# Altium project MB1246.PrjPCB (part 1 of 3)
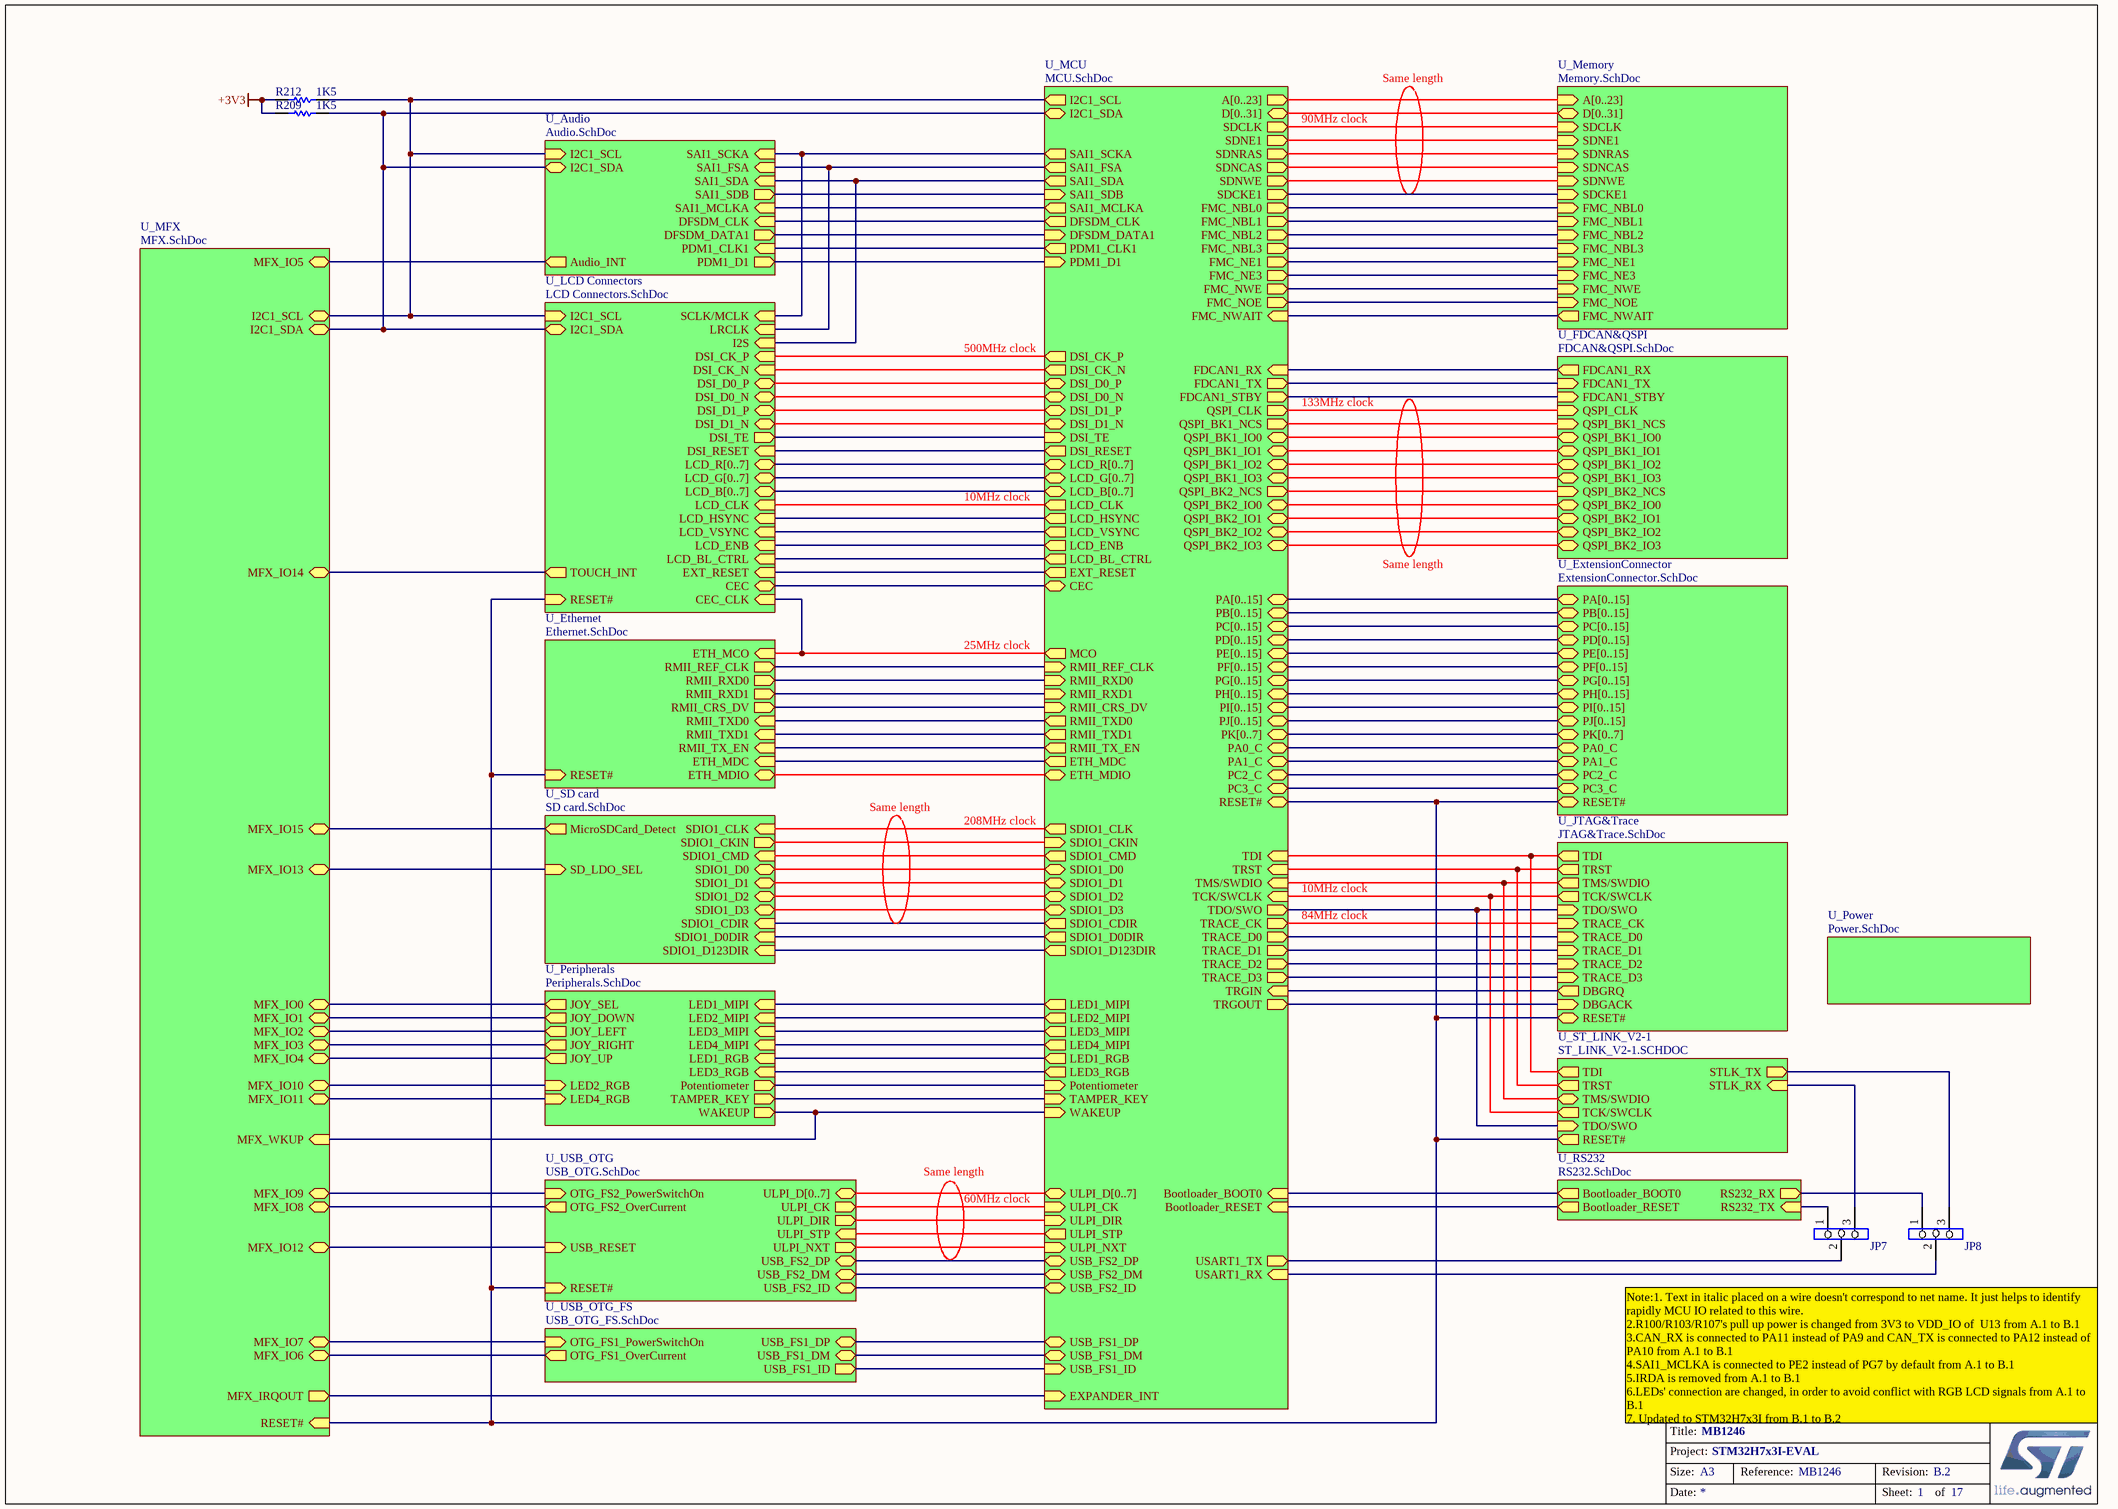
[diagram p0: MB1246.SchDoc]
17 sheets, 671 parts. Net scope: hierarchical (ports join the sheet entries above them; power ports are global).
Sheets:
  MB1246.SchDoc
    U_Audio = Audio.SchDoc
    U_ExtensionConnector = ExtensionConnector.SchDoc
    U_FDCAN&QSPI = FDCAN&QSPI.SchDoc
    U_Memory = Memory.SchDoc
    U_MFX = MFX.SchDoc
    U_Power = Power.SchDoc
    U_ST_LINK_V2-1 = ST_LINK_V2-1.SCHDOC
    U_USB_OTG_FS = USB_OTG_FS.SchDoc
    U_SD card = SD card.SchDoc
    U_JTAG&Trace = JTAG&Trace.SchDoc
    U_Ethernet = Ethernet.SchDoc
    U_RS232 = RS232.SchDoc
    U_Peripherals = Peripherals.SchDoc
    U_MCU = MCU.SchDoc
    U_USB_OTG = USB_OTG.SchDoc
    U_LCD Connectors = LCD Connectors.SchDoc

## Sheet MB1246.SchDoc: MB1246
size A3; DocumentNumber: MB1246; Revision: B.2; SheetNumber: 1; SheetTotal: 17; Project: STM32H7x3I-EVAL

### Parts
JP7  (no value)  [SIP3]
JP8  (no value)  [SIP3]
R209  1K5  [0603R]
R212  1K5  [0603R]

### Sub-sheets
U_Audio = Audio.SchDoc: SAI1_SCKA (in), SAI1_FSA (in), SAI1_SDA (in), SAI1_SDB (out), Audio_INT (out), I2C1_SDA (bidir), I2C1_SCL (in), SAI1_MCLKA (in), DFSDM_CLK (in), DFSDM_DATA1 (out), PDM1_CLK1 (in), PDM1_D1 (out)
U_Ethernet = Ethernet.SchDoc: ETH_MCO (in), RMII_TXD0 (in), RMII_TX_EN (in), RMII_RXD0 (out), RMII_REF_CLK (out), RMII_CRS_DV (out), ETH_MDC (in), ETH_MDIO (bidir), RMII_TXD1 (in), RMII_RXD1 (out), RESET# (in)
U_ExtensionConnector = ExtensionConnector.SchDoc: PA[0..15] (bidir), PB[0..15] (bidir), PC[0..15] (bidir), PD[0..15] (bidir), PE[0..15] (bidir), PF[0..15] (bidir), PG[0..15] (bidir), PH[0..15] (bidir), PI[0..15] (bidir), PJ[0..15] (bidir), PK[0..7] (bidir), RESET# (bidir), PA0_C (bidir), PA1_C (bidir), PC2_C (bidir), PC3_C (bidir)
U_FDCAN&QSPI = FDCAN&QSPI.SchDoc: FDCAN1_TX (in), FDCAN1_RX (out), FDCAN1_STBY (in), QSPI_BK1_IO3 (bidir), QSPI_BK1_IO1 (bidir), QSPI_BK1_NCS (in), QSPI_BK1_IO0 (bidir), QSPI_BK1_IO2 (bidir), QSPI_CLK (in), QSPI_BK2_NCS (in), QSPI_BK2_IO0 (bidir), QSPI_BK2_IO1 (bidir), QSPI_BK2_IO2 (bidir), QSPI_BK2_IO3 (bidir)
U_JTAG&Trace = JTAG&Trace.SchDoc: TDI (out), RESET# (bidir), TRACE_D3 (in), TRACE_D2 (in), TRACE_D1 (in), TRACE_D0 (in), TRACE_CK (in), TRST (out), TMS/SWDIO (out), TCK/SWCLK (out), TDO/SWO (in), DBGRQ (out), DBGACK (in)
U_LCD Connectors = LCD Connectors.SchDoc: LCD_R[0..7] (bidir), LCD_HSYNC (in), LCD_VSYNC (in), LCD_CLK (in), LCD_ENB (in), I2C1_SDA (bidir), I2C1_SCL (in), LCD_B[0..7] (bidir), LCD_G[0..7] (bidir), TOUCH_INT (out), EXT_RESET (in), DSI_CK_P (in), DSI_CK_N (in), DSI_D0_P (bidir), DSI_D0_N (bidir), DSI_D1_P (bidir), DSI_D1_N (bidir), LCD_BL_CTRL (in), DSI_TE (out), DSI_RESET (in), SCLK/MCLK (in), LRCLK (in), I2S (in), CEC (bidir), CEC_CLK (in), RESET# (in)
U_MCU = MCU.SchDoc: PA[0..15] (bidir), PB[0..15] (bidir), PC[0..15] (bidir), PD[0..15] (bidir), PE[0..15] (bidir), PF[0..15] (bidir), PG[0..15] (bidir), PH[0..15] (bidir), PI[0..15] (bidir), TMS/SWDIO (in), TCK/SWCLK (in), TDI (in), ULPI_STP (out), ETH_MDC (out), RMII_RXD0 (in), RMII_RXD1 (in), SDIO1_D0 (bidir), EXT_RESET (out), SDIO1_CLK (out), TAMPER_KEY (in), LCD_ENB (out), SDIO1_CMD (out), FMC_NOE (out), FMC_NWE (out), FMC_NWAIT (in), FMC_NE1 (out), FMC_NBL3 (out), FMC_NBL2 (out), EXPANDER_INT (in), ULPI_DIR (in), LCD_HSYNC (out), LCD_VSYNC (out), LCD_CLK (out), FMC_NBL0 (out), FMC_NBL1 (out), TRACE_CK (out), TRACE_D0 (out), TRACE_D2 (out), TRACE_D1 (out), SAI1_SDA (out), TRACE_D3 (out), SAI1_SDB (in), SAI1_SCKA (out), SAI1_FSA (out), SAI1_MCLKA (out), SDNRAS (out), SDCLK (out), FMC_NE3 (out), RMII_TX_EN (out), RMII_TXD1 (out), SDNCAS (out), SDCKE1 (out), SDNE1 (out), ULPI_NXT (in), SDNWE (out), LCD_G[0..7] (bidir), LCD_B[0..7] (bidir), D[0..31] (bidir), A[0..23] (out), ULPI_D[0..7] (bidir), PJ[0..15] (bidir), PK[0..7] (bidir), LCD_R[0..7] (bidir), QSPI_BK1_IO3 (bidir), QSPI_BK1_IO2 (bidir), QSPI_BK1_IO1 (bidir), QSPI_BK1_IO0 (bidir), DSI_TE (in), DSI_CK_P (out), DSI_CK_N (out), DSI_D0_P (bidir), DSI_D0_N (bidir), DSI_D1_P (bidir), DSI_D1_N (bidir), DSI_RESET (out), LED1_MIPI (out), LED2_MIPI (out), LED3_MIPI (out), LED4_MIPI (out), RMII_REF_CLK (in), ETH_MDIO (bidir), ULPI_CK (in), RMII_CRS_DV (in), LCD_BL_CTRL (out), USART1_TX (out), USART1_RX (in), USB_FS1_ID (in), FDCAN1_RX (in), USB_FS1_DM (bidir), FDCAN1_TX (out), USB_FS1_DP (bidir), MCO (out), WAKEUP (in), TDO/SWO (out), TRST (in), I2C1_SCL (out), I2C1_SDA (bidir), USB_FS2_ID (bidir), USB_FS2_DM (bidir), USB_FS2_DP (bidir), QSPI_BK1_NCS (out), RMII_TXD0 (out), QSPI_CLK (out), SDIO1_CKIN (in), SDIO1_CDIR (out), DFSDM_CLK (out), DFSDM_DATA1 (in), SDIO1_D0DIR (out), SDIO1_D123DIR (out), SDIO1_D1 (bidir), SDIO1_D2 (bidir), SDIO1_D3 (bidir), FDCAN1_STBY (out), PDM1_CLK1 (out), PDM1_D1 (in), QSPI_BK2_IO2 (bidir), QSPI_BK2_IO3 (bidir), QSPI_BK2_IO0 (bidir), QSPI_BK2_IO1 (bidir), RESET# (bidir), Bootloader_BOOT0 (in), Bootloader_RESET (in), PA0_C (bidir), PA1_C (bidir), PC2_C (bidir), PC3_C (bidir), QSPI_BK2_NCS (out), CEC (bidir), Potentiometer (in), TRGOUT (out), TRGIN (in), LED1_RGB (out), LED3_RGB (out)
U_Memory = Memory.SchDoc: FMC_NE1 (in), FMC_NWE (in), FMC_NOE (in), FMC_NWAIT (out), FMC_NBL0 (in), FMC_NBL1 (in), D[0..31] (bidir), A[0..23] (in), SDNCAS (in), SDNWE (in), SDNRAS (in), SDNE1 (in), SDCKE1 (in), SDCLK (in), FMC_NBL3 (in), FMC_NBL2 (in), FMC_NE3 (in)
U_MFX = MFX.SchDoc: MFX_IRQOUT (out), I2C1_SDA (bidir), I2C1_SCL (bidir), MFX_IO5 (bidir), MFX_IO6 (bidir), MFX_IO7 (bidir), MFX_IO8 (bidir), MFX_IO9 (bidir), MFX_IO10 (bidir), MFX_IO11 (bidir), MFX_IO12 (bidir), MFX_IO13 (bidir), MFX_IO14 (bidir), MFX_IO15 (bidir), MFX_WKUP (in), MFX_IO0 (bidir), MFX_IO1 (bidir), MFX_IO2 (bidir), MFX_IO3 (bidir), MFX_IO4 (bidir), RESET# (in)
U_Peripherals = Peripherals.SchDoc: JOY_SEL (out), JOY_DOWN (out), JOY_LEFT (out), JOY_RIGHT (out), JOY_UP (out), TAMPER_KEY (out), WAKEUP (out), Potentiometer (out), LED4_MIPI (in), LED3_MIPI (in), LED1_MIPI (in), LED2_MIPI (in), LED1_RGB (in), LED2_RGB (in), LED3_RGB (in), LED4_RGB (in)
U_Power = Power.SchDoc: no entries
U_RS232 = RS232.SchDoc: RS232_TX (in), RS232_RX (out), Bootloader_BOOT0 (out), Bootloader_RESET (out)
U_SD card = SD card.SchDoc: SDIO1_CKIN (out), SDIO1_CDIR (in), SDIO1_D0DIR (in), SDIO1_D123DIR (in), SDIO1_D0 (bidir), SDIO1_D1 (bidir), SDIO1_D2 (bidir), SDIO1_D3 (bidir), SDIO1_CMD (in), SDIO1_CLK (in), SD_LDO_SEL (in), MicroSDCard_Detect (out)
U_ST_LINK_V2-1 = ST_LINK_V2-1.SCHDOC: STLK_RX (in), STLK_TX (out), TDI (out), TRST (out), TMS/SWDIO (bidir), TCK/SWCLK (out), TDO/SWO (in), RESET# (out)
U_USB_OTG = USB_OTG.SchDoc: ULPI_D[0..7] (bidir), ULPI_CK (out), ULPI_DIR (out), ULPI_NXT (out), ULPI_STP (in), USB_RESET (in), USB_FS2_DM (bidir), USB_FS2_DP (bidir), OTG_FS2_PowerSwitchOn (in), OTG_FS2_OverCurrent (out), USB_FS2_ID (bidir), RESET# (in)
U_USB_OTG_FS = USB_OTG_FS.SchDoc: OTG_FS1_PowerSwitchOn (in), OTG_FS1_OverCurrent (out), USB_FS1_DM (bidir), USB_FS1_DP (bidir), USB_FS1_ID (out)

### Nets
+3V3: R209.1 R212.1
BK2_IO0: sheet U_FDCAN&QSPI/QSPI_BK2_IO0, sheet U_MCU/QSPI_BK2_IO0
BK2_IO1: sheet U_FDCAN&QSPI/QSPI_BK2_IO1, sheet U_MCU/QSPI_BK2_IO1
BK2_IO2: sheet U_FDCAN&QSPI/QSPI_BK2_IO2, sheet U_MCU/QSPI_BK2_IO2
BK2_IO3: sheet U_FDCAN&QSPI/QSPI_BK2_IO3, sheet U_MCU/QSPI_BK2_IO3
I2C1_SCL: R212.2 ; sheet U_Audio/I2C1_SCL, sheet U_MFX/I2C1_SCL, sheet U_MCU/I2C1_SCL, sheet U_LCD Connectors/I2C1_SCL
I2C1_SDA: R209.2 ; sheet U_Audio/I2C1_SDA, sheet U_MFX/I2C1_SDA, sheet U_MCU/I2C1_SDA, sheet U_LCD Connectors/I2C1_SDA
LCD_B0: sheet U_JTAG&Trace/DBGACK, sheet U_MCU/TRGOUT
LCD_B4: sheet U_Peripherals/LED1_MIPI, sheet U_MCU/LED1_MIPI
LCD_B5: sheet U_Peripherals/LED2_MIPI, sheet U_MCU/LED2_MIPI
LCD_B6: sheet U_Peripherals/LED3_MIPI, sheet U_MCU/LED3_MIPI
LCD_B7: sheet U_Peripherals/LED4_MIPI, sheet U_MCU/LED4_MIPI
LCD_BL_CTRL: sheet U_MCU/LCD_BL_CTRL, sheet U_LCD Connectors/LCD_BL_CTRL
LCD_G0: sheet U_JTAG&Trace/DBGRQ, sheet U_MCU/TRGIN
LCD_R3: sheet U_MCU/DSI_TE, sheet U_LCD Connectors/DSI_TE
NCS2: sheet U_FDCAN&QSPI/QSPI_BK2_NCS, sheet U_MCU/QSPI_BK2_NCS
PA0: sheet U_MFX/MFX_WKUP, sheet U_Peripherals/WAKEUP, sheet U_MCU/WAKEUP
PA0_C: sheet U_ExtensionConnector/PA0_C, sheet U_MCU/PA0_C
PA1: sheet U_Ethernet/RMII_REF_CLK, sheet U_MCU/RMII_REF_CLK
PA1_C: sheet U_ExtensionConnector/PA1_C, sheet U_MCU/PA1_C
PA2: sheet U_Ethernet/ETH_MDIO, sheet U_MCU/ETH_MDIO
PA4: sheet U_Peripherals/LED3_RGB, sheet U_MCU/EXT_RESET, sheet U_MCU/LED3_RGB, sheet U_LCD Connectors/EXT_RESET
PA5: sheet U_MCU/ULPI_CK, sheet U_USB_OTG/ULPI_CK
PA7: sheet U_Ethernet/RMII_CRS_DV, sheet U_MCU/RMII_CRS_DV
PA8: sheet U_Ethernet/ETH_MCO, sheet U_MCU/MCO, sheet U_LCD Connectors/CEC_CLK
PA10: sheet U_USB_OTG_FS/USB_FS1_ID, sheet U_MCU/USB_FS1_ID
PA13: sheet U_ST_LINK_V2-1/TMS/SWDIO, sheet U_JTAG&Trace/TMS/SWDIO, sheet U_MCU/TMS/SWDIO
PA14: sheet U_ST_LINK_V2-1/TCK/SWCLK, sheet U_JTAG&Trace/TCK/SWCLK, sheet U_MCU/TCK/SWCLK
PA15: sheet U_ST_LINK_V2-1/TDI, sheet U_JTAG&Trace/TDI, sheet U_MCU/TDI, sheet U_MCU/CEC, sheet U_LCD Connectors/CEC
PB2: sheet U_FDCAN&QSPI/QSPI_CLK, sheet U_MCU/QSPI_CLK
PB3: sheet U_ST_LINK_V2-1/TDO/SWO, sheet U_JTAG&Trace/TDO/SWO, sheet U_MCU/TDO/SWO
PB4: sheet U_ST_LINK_V2-1/TRST, sheet U_JTAG&Trace/TRST, sheet U_MCU/TRST
PB8: sheet U_SD card/SDIO1_CKIN, sheet U_MCU/SDIO1_CKIN
PB9: sheet U_SD card/SDIO1_CDIR, sheet U_MCU/SDIO1_CDIR
PC0: sheet U_MCU/ULPI_STP, sheet U_USB_OTG/ULPI_STP
PC1: sheet U_Audio/PDM1_D1, sheet U_MCU/PDM1_D1
PC2: sheet U_Audio/DFSDM_CLK, sheet U_MCU/DFSDM_CLK
PC2_C: sheet U_ExtensionConnector/PC2_C, sheet U_MCU/PC2_C
PC3: sheet U_Audio/DFSDM_DATA1, sheet U_MCU/DFSDM_DATA1
PC3_C: sheet U_ExtensionConnector/PC3_C, sheet U_MCU/PC3_C
PC4: sheet U_Ethernet/RMII_RXD0, sheet U_MCU/RMII_RXD0
PC5: sheet U_Ethernet/RMII_RXD1, sheet U_MCU/RMII_RXD1
PC7: sheet U_SD card/SDIO1_D123DIR, sheet U_MCU/SDIO1_D123DIR
PC8: sheet U_SD card/SDIO1_D0, sheet U_MCU/SDIO1_D0
PC9: sheet U_SD card/SDIO1_D1, sheet U_MCU/SDIO1_D1
PC10: sheet U_SD card/SDIO1_D2, sheet U_MCU/SDIO1_D2
PC11: sheet U_SD card/SDIO1_D3, sheet U_MCU/SDIO1_D3
PC12: sheet U_SD card/SDIO1_CLK, sheet U_MCU/SDIO1_CLK
PC13: sheet U_Peripherals/TAMPER_KEY, sheet U_MCU/TAMPER_KEY
PD2: sheet U_SD card/SDIO1_CMD, sheet U_MCU/SDIO1_CMD
PD3: sheet U_FDCAN&QSPI/FDCAN1_STBY, sheet U_MCU/FDCAN1_STBY
PD4: sheet U_Memory/FMC_NOE, sheet U_MCU/FMC_NOE
PD5: sheet U_Memory/FMC_NWE, sheet U_MCU/FMC_NWE
PD6: sheet U_Memory/FMC_NWAIT, sheet U_MCU/FMC_NWAIT
PD7: sheet U_Memory/FMC_NE1, sheet U_MCU/FMC_NE1
PE0: sheet U_Memory/FMC_NBL0, sheet U_MCU/FMC_NBL0
PE1: sheet U_Memory/FMC_NBL1, sheet U_MCU/FMC_NBL1
PF6: sheet U_FDCAN&QSPI/QSPI_BK1_IO3, sheet U_MCU/QSPI_BK1_IO3
PF7: sheet U_FDCAN&QSPI/QSPI_BK1_IO2, sheet U_MCU/QSPI_BK1_IO2
PF8: sheet U_FDCAN&QSPI/QSPI_BK1_IO0, sheet U_MCU/QSPI_BK1_IO0
PF9: sheet U_FDCAN&QSPI/QSPI_BK1_IO1, sheet U_MCU/QSPI_BK1_IO1
PF10: sheet U_Peripherals/LED1_RGB, sheet U_MCU/DSI_RESET, sheet U_MCU/LED1_RGB, sheet U_LCD Connectors/DSI_RESET
PF11: sheet U_Memory/SDNRAS, sheet U_MCU/SDNRAS
PG6: sheet U_FDCAN&QSPI/QSPI_BK1_NCS, sheet U_MCU/QSPI_BK1_NCS
PG8: sheet U_Memory/SDCLK, sheet U_MCU/SDCLK
PG10: sheet U_Memory/FMC_NE3, sheet U_MCU/FMC_NE3
PG11: sheet U_Ethernet/RMII_TX_EN, sheet U_MCU/RMII_TX_EN
PG12: sheet U_Ethernet/RMII_TXD1, sheet U_MCU/RMII_TXD1
PG13: sheet U_Ethernet/RMII_TXD0, sheet U_MCU/RMII_TXD0
PG15: sheet U_Memory/SDNCAS, sheet U_MCU/SDNCAS
PH4: sheet U_MCU/ULPI_NXT, sheet U_USB_OTG/ULPI_NXT
PH5: sheet U_Memory/SDNWE, sheet U_MCU/SDNWE
PH6: sheet U_Memory/SDNE1, sheet U_MCU/SDNE1
PH7: sheet U_Memory/SDCKE1, sheet U_MCU/SDCKE1
PI4: sheet U_Memory/FMC_NBL2, sheet U_MCU/FMC_NBL2
PI5: sheet U_Memory/FMC_NBL3, sheet U_MCU/FMC_NBL3
PI8: sheet U_MFX/MFX_IRQOUT, sheet U_MCU/EXPANDER_INT
PI11: sheet U_MCU/ULPI_DIR, sheet U_USB_OTG/ULPI_DIR
PI12: sheet U_MCU/LCD_HSYNC, sheet U_LCD Connectors/LCD_HSYNC
PI13: sheet U_MCU/LCD_VSYNC, sheet U_LCD Connectors/LCD_VSYNC
PI14: sheet U_MCU/LCD_CLK, sheet U_LCD Connectors/LCD_CLK
PK7: sheet U_MCU/LCD_ENB, sheet U_LCD Connectors/LCD_ENB
RESET#: sheet U_ExtensionConnector/RESET#, sheet U_MFX/RESET#, sheet U_ST_LINK_V2-1/RESET#, sheet U_JTAG&Trace/RESET#, sheet U_Ethernet/RESET#, sheet U_MCU/RESET#, sheet U_USB_OTG/RESET#, sheet U_LCD Connectors/RESET#
SAI1_MCLKA: sheet U_Audio/SAI1_MCLKA, sheet U_MCU/SAI1_MCLKA
STLINK_RX: JP7.3 ; sheet U_ST_LINK_V2-1/STLK_RX
STLINK_TX: JP8.3 ; sheet U_ST_LINK_V2-1/STLK_TX
TOUCH_INT: sheet U_MFX/MFX_IO14, sheet U_LCD Connectors/TOUCH_INT
NetB4_1: sheet U_MFX/MFX_IO2, sheet U_Peripherals/JOY_LEFT
NetB4_2: sheet U_MFX/MFX_IO0, sheet U_Peripherals/JOY_SEL
NetB4_3: sheet U_MFX/MFX_IO1, sheet U_Peripherals/JOY_DOWN
NetB4_4: sheet U_MFX/MFX_IO3, sheet U_Peripherals/JOY_RIGHT
NetB4_6: sheet U_MFX/MFX_IO4, sheet U_Peripherals/JOY_UP
NetCN8_12: sheet U_JTAG&Trace/TRACE_CK, sheet U_MCU/TRACE_CK
NetCN8_14: sheet U_JTAG&Trace/TRACE_D0, sheet U_MCU/TRACE_D0
NetCN8_16: sheet U_JTAG&Trace/TRACE_D1, sheet U_MCU/TRACE_D1
NetCN8_18: sheet U_JTAG&Trace/TRACE_D2, sheet U_MCU/TRACE_D2
NetCN8_20: sheet U_JTAG&Trace/TRACE_D3, sheet U_MCU/TRACE_D3
NetCN13_10: sheet U_MFX/MFX_IO15, sheet U_SD card/MicroSDCard_Detect
NetCN15_3: sheet U_MCU/DSI_CK_P, sheet U_LCD Connectors/DSI_CK_P
NetCN15_5: sheet U_MCU/DSI_CK_N, sheet U_LCD Connectors/DSI_CK_N
NetCN15_9: sheet U_MCU/DSI_D0_P, sheet U_LCD Connectors/DSI_D0_P
NetCN15_11: sheet U_MCU/DSI_D0_N, sheet U_LCD Connectors/DSI_D0_N
NetCN15_15: sheet U_MCU/DSI_D1_P, sheet U_LCD Connectors/DSI_D1_P
NetCN15_17: sheet U_MCU/DSI_D1_N, sheet U_LCD Connectors/DSI_D1_N
NetCN15_35: sheet U_Audio/SAI1_SCKA, sheet U_MCU/SAI1_SCKA, sheet U_LCD Connectors/SCLK/MCLK
NetCN15_37: sheet U_Audio/SAI1_FSA, sheet U_MCU/SAI1_FSA, sheet U_LCD Connectors/LRCLK
NetCN15_39: sheet U_Audio/SAI1_SDA, sheet U_MCU/SAI1_SDA, sheet U_LCD Connectors/I2S
NetCN16_2: sheet U_MCU/USB_FS2_DM, sheet U_USB_OTG/USB_FS2_DM
NetCN16_3: sheet U_MCU/USB_FS2_DP, sheet U_USB_OTG/USB_FS2_DP
NetCN16_4: sheet U_MCU/USB_FS2_ID, sheet U_USB_OTG/USB_FS2_ID
NetCN18_2: sheet U_USB_OTG_FS/USB_FS1_DM, sheet U_MCU/USB_FS1_DM
NetCN18_3: sheet U_USB_OTG_FS/USB_FS1_DP, sheet U_MCU/USB_FS1_DP
NetD3_1: sheet U_RS232/Bootloader_BOOT0, sheet U_MCU/Bootloader_BOOT0
NetJP2_2: sheet U_FDCAN&QSPI/FDCAN1_TX, sheet U_MCU/FDCAN1_TX
NetJP6_2: sheet U_RS232/Bootloader_RESET, sheet U_MCU/Bootloader_RESET
NetJP7_1: JP7.1 ; sheet U_RS232/RS232_TX
NetJP7_2: JP7.2 ; sheet U_MCU/USART1_TX
NetJP8_1: JP8.1 ; sheet U_RS232/RS232_RX
NetJP8_2: JP8.2 ; sheet U_MCU/USART1_RX
NetM1_1: sheet U_MFX/MFX_IO13, sheet U_SD card/SD_LDO_SEL
NetM1_23: sheet U_SD card/SDIO1_D0DIR, sheet U_MCU/SDIO1_D0DIR
NetR12_2: sheet U_Peripherals/Potentiometer, sheet U_MCU/Potentiometer
NetR126_1: sheet U_MFX/MFX_IO8, sheet U_USB_OTG/OTG_FS2_OverCurrent
NetR141_2: sheet U_MFX/MFX_IO7, sheet U_USB_OTG_FS/OTG_FS1_PowerSwitchOn
NetR146_1: sheet U_MFX/MFX_IO6, sheet U_USB_OTG_FS/OTG_FS1_OverCurrent
NetR295_1: sheet U_MFX/MFX_IO10, sheet U_Peripherals/LED2_RGB
NetR297_1: sheet U_MFX/MFX_IO11, sheet U_Peripherals/LED4_RGB
NetSB8_1: sheet U_Audio/SAI1_SDB, sheet U_MCU/SAI1_SDB
NetSB11_1: sheet U_Audio/PDM1_CLK1, sheet U_MCU/PDM1_CLK1
NetSB29_1: sheet U_MFX/MFX_IO9, sheet U_USB_OTG/OTG_FS2_PowerSwitchOn
NetSB38_1: sheet U_Ethernet/ETH_MDC, sheet U_MCU/ETH_MDC
NetSB50_1: sheet U_FDCAN&QSPI/FDCAN1_RX, sheet U_MCU/FDCAN1_RX
NetSB61_1: sheet U_MFX/MFX_IO12, sheet U_USB_OTG/USB_RESET
NetU22_G3: sheet U_Audio/Audio_INT, sheet U_MFX/MFX_IO5

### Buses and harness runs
bus sheet U_ExtensionConnector/PA[0..15] = sheet U_MCU/PA[0..15]
bus sheet U_ExtensionConnector/PB[0..15] = sheet U_MCU/PB[0..15]
bus sheet U_ExtensionConnector/PC[0..15] = sheet U_MCU/PC[0..15]
bus sheet U_ExtensionConnector/PD[0..15] = sheet U_MCU/PD[0..15]
bus sheet U_ExtensionConnector/PE[0..15] = sheet U_MCU/PE[0..15]
bus sheet U_ExtensionConnector/PF[0..15] = sheet U_MCU/PF[0..15]
bus sheet U_ExtensionConnector/PG[0..15] = sheet U_MCU/PG[0..15]
bus sheet U_ExtensionConnector/PH[0..15] = sheet U_MCU/PH[0..15]
bus sheet U_ExtensionConnector/PI[0..15] = sheet U_MCU/PI[0..15]
bus sheet U_ExtensionConnector/PJ[0..15] = sheet U_MCU/PJ[0..15]
bus sheet U_ExtensionConnector/PK[0..7] = sheet U_MCU/PK[0..7]
bus sheet U_LCD Connectors/LCD_B[0..7] = sheet U_MCU/LCD_B[0..7]
bus sheet U_LCD Connectors/LCD_G[0..7] = sheet U_MCU/LCD_G[0..7]
bus sheet U_LCD Connectors/LCD_R[0..7] = sheet U_MCU/LCD_R[0..7]
bus sheet U_MCU/A[0..23] = sheet U_Memory/A[0..23]
bus sheet U_MCU/D[0..31] = sheet U_Memory/D[0..31]
bus sheet U_MCU/ULPI_D[0..7] = sheet U_USB_OTG/ULPI_D[0..7]

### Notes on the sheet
- Same length
- 90MHz clock
- 500MHz clock
- 133MHz clock
- 10MHz clock
- 25MHz clock
- 208MHz clock
- 84MHz clock
- 60MHz clock
- Note:1. Text in italic placed on a wire doesn't correspond to net name. It just helps to identify rapidly MCU IO related to this wire.
  2.R100/R103/R107's pull up power is changed from 3V3 to VDD_IO of  U13 from A.1 to B.1
  3.CAN_RX is connected to PA11 instead of PA9 and CAN_TX is connected to PA12 instead of PA10 from A.1 to B.1
  4.SAI1_MCLKA is connected to PE2 instead of PG7 by default from A.1 to B.1
  5.IRDA is removed from A.1 to B.1
  6.LEDs' connection are changed, in order to avoid conflict with RGB LCD signals from A.1 to B.1
  7. Updated to STM32H7x3I from B.1 to B.2

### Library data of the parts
JP7 JP8 = Jumper3
R209 R212 = Res1: Resistor; Value: 1K

## Sheet Audio.SchDoc: Audio
size A4; DocumentNumber: MB1246; Revision: B.2; SheetNumber: 5; SheetTotal: 17; Project: STM32H7x3I-EVAL
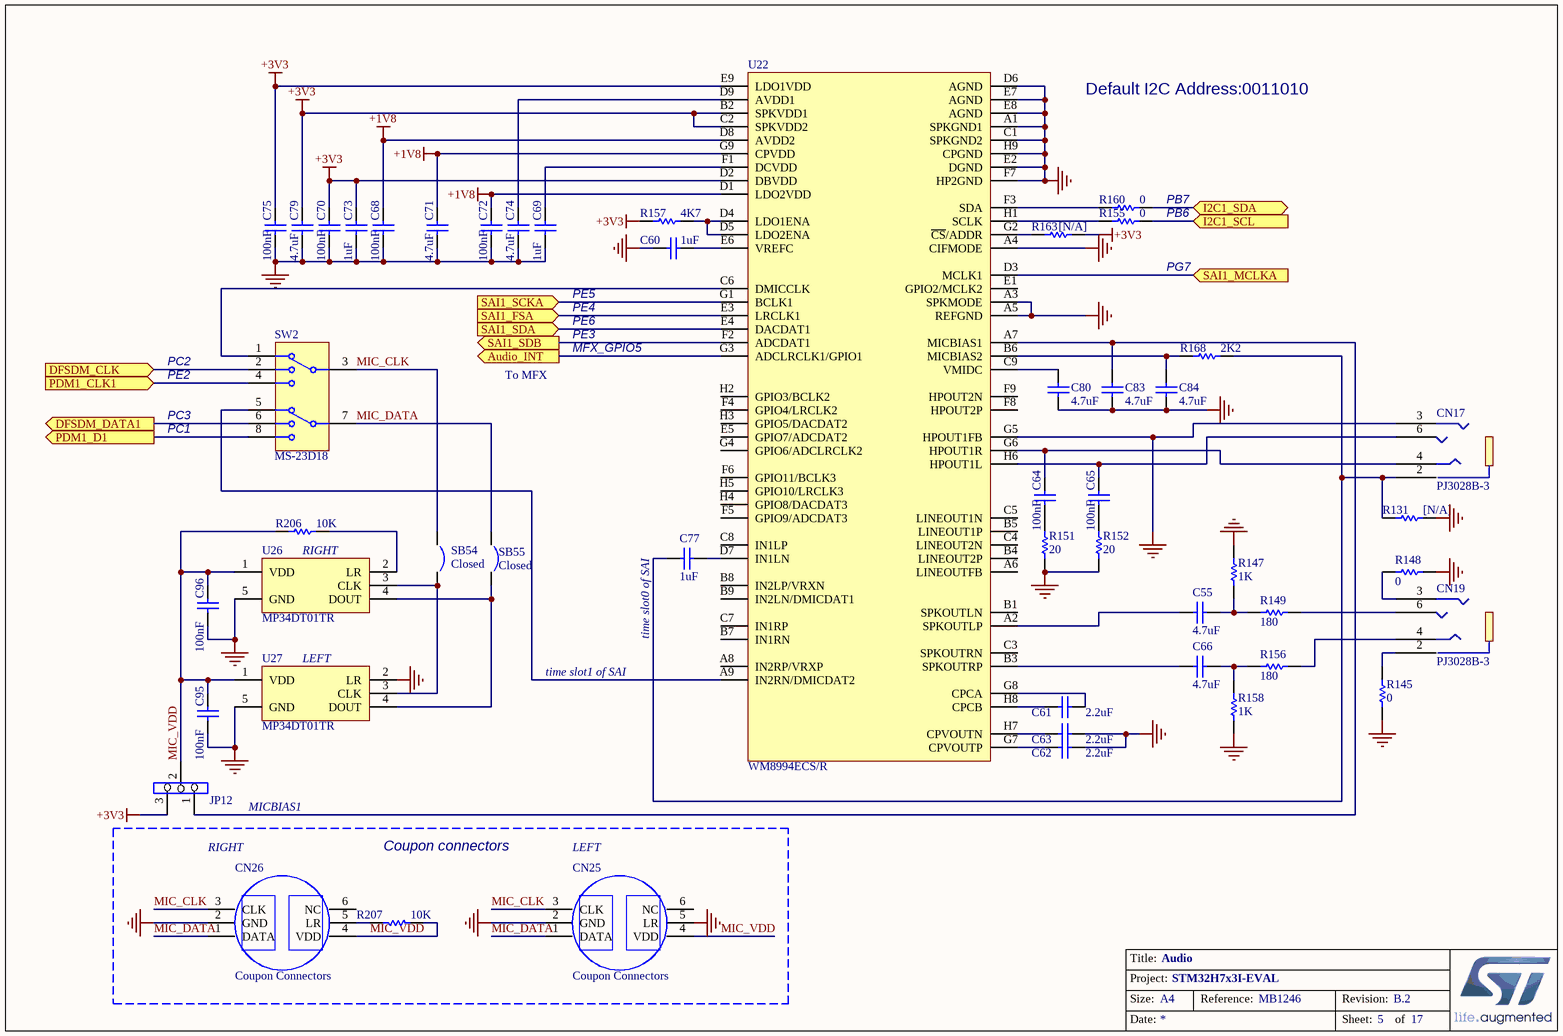
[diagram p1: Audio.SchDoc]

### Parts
C55  4.7uF  [0603C]
C60  1uF  [0603C]
C61  2.2uF  [0603C]
C62  2.2uF  [0603C]
C63  2.2uF  [0603C]
C64  100nF  [0603C]
C65  100nF  [0603C]
C66  4.7uF  [0603C]
C68  100nF  [0603C]
C69  1uF  [0603C]
C70  100nF  [0603C]
C71  4.7uF  [0603C]
C72  100nF  [0603C]
C73  1uF  [0603C]
C74  4.7uF  [0603C]
C75  100nF  [0603C]
C77  1uF  [0603C]
C79  4.7uF  [0603C]
C80  4.7uF  [0603C]
C83  4.7uF  [0603C]
C84  4.7uF  [0603C]
C95  100nF  [0603C]
C96  100nF  [0603C]
CN17  PJ3028B-3  [PJ3028B]
CN19  PJ3028B-3  [PJ3028B]
CN25  Coupon Connectors  [Coupon]
CN26  Coupon Connectors  [Coupon]
JP12  (no value)  [SIP3]
R131  [N/A]  [0603R]
R145  0  [0603R]
R147  1K  [0402R]
R148  0  [0603R]
R149  180  [0402R]
R151  20  [0603R]
R152  20  [0603R]
R155  0  [0603R]
R156  180  [0402R]
R157  4K7  [0603R]
R158  1K  [0402R]
R160  0  [0603R]
R163  [N/A]  [0603R]
R168  2K2  [0603R]
R206  10K  [0603R]
R207  10K  [0603R]
SB54  Closed  [SB_0603]
SB55  Closed  [SB_0603]
SW2  MS-23D18  [SW1_8TH_13X3R5]
U22  WM8994ECS/R  [BGA72_0R5_4R5X4]
U26  MP34DT01TR  [MP34DT01TR]
U27  MP34DT01TR  [MP34DT01TR]

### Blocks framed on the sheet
Coupon connectors: CN25 CN26 R207

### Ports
Audio_INT (out), DFSDM_CLK (in), DFSDM_DATA1 (out), I2C1_SCL (in), I2C1_SDA (bidir), PDM1_CLK1 (in), PDM1_D1 (out), SAI1_FSA (in), SAI1_MCLKA (in), SAI1_SCKA (in), SAI1_SDA (in), SAI1_SDB (out)

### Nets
+1V8: C68.1 C71.1 C72.1 U22.D1(LDO2VDD) U22.D8(AVDD2) U22.G9(CPVDD)
+3V3: C70.1 C73.1 C75.1 C79.1 JP12.3 R157.2 R163.1 U22.B2(SPKVDD1) U22.C2(SPKVDD2) U22.D2(DBVDD) U22.E9(LDO1VDD)
GND: C60.2 C62.2 C63.2 C68.2 C69.2 C70.2 C71.2 C72.2 C73.2 C74.2 C75.2 C79.2 C80.1 C83.1 C84.1 C95.2 C96.2 CN17.3 CN25.2(GND) CN25.5(LR) CN26.2(GND) R131.1 R145.2 R147.2 R148.2 R151.2 R152.2 R158.1 U22.A1(SPKGND1) U22.A3(SPKMODE) U22.A4(CIFMODE) U22.A5(REFGND) U22.C1(SPKGND2) U22.D6(AGND) U22.E2(DGND) U22.E7(AGND) U22.E8(AGND) U22.F7(HP2GND) U22.G5(HPOUT1FB) U22.H9(CPGND) U26.5(GND) U27.2(LR) U27.5(GND)
I2C1_SCL: R155.1 ; port I2C1_SCL
I2C1_SDA: R160.1 ; port I2C1_SDA
MIC_CLK: CN25.3(CLK) CN26.3(CLK) SB54.1 SW2.3
MIC_DATA: CN25.1(DATA) CN26.1(DATA) SB55.1 SW2.7
MIC_VDD: C95.1 C96.1 CN25.4(VDD) CN26.4(VDD) JP12.2 R206.2 R207.2 U26.1(VDD) U27.1(VDD)
PC1: SW2.8 ; port PDM1_D1
PC2: SW2.2 ; port DFSDM_CLK
PC3: SW2.6 ; port DFSDM_DATA1
SAI1_MCLKA: U22.D3(MCLK1) ; port SAI1_MCLKA
NetC55_1: C55.1 R147.1 R149.1
NetC55_2: C55.2 U22.A2(SPKOUTLP)
NetC60_1: C60.1 U22.E6(VREFC)
NetC61_1: C61.1 U22.H8(CPCB)
NetC61_2: C61.2 U22.G8(CPCA)
NetC62_1: C62.1 U22.G7(CPVOUTP)
NetC63_1: C63.1 U22.H7(CPVOUTN)
NetC64_1: C64.1 CN17.4 U22.G6(HPOUT1R)
NetC64_2: C64.2 R151.1
NetC65_1: C65.1 CN17.6 U22.H6(HPOUT1L)
NetC65_2: C65.2 R152.1
NetC66_1: C66.1 R156.2 R158.2
NetC66_2: C66.2 U22.B3(SPKOUTRP)
NetC69_1: C69.1 U22.F1(DCVDD)
NetC74_1: C74.1 U22.D9(AVDD1)
NetC77_1: C77.1 U22.D7(IN1LN)
NetC77_2: C77.2 CN17.2 R131.2 R168.1
NetC80_2: C80.2 U22.C9(VMIDC)
NetC83_2: C83.2 JP12.1 U22.A7(MICBIAS1)
NetC84_2: C84.2 R168.2 U22.B6(MICBIAS2)
NetCN15_35: U22.G1(BCLK1) ; port SAI1_SCKA
NetCN15_37: U22.E3(LRCLK1) ; port SAI1_FSA
NetCN15_39: U22.E4(DACDAT1) ; port SAI1_SDA
NetCN19_2: CN19.2 R145.1
NetCN19_3: CN19.3 R148.1
NetCN19_4: CN19.4 R156.1
NetCN19_6: CN19.6 R149.2
NetCN26_5: CN26.5(LR) R207.1
NetR155_2: R155.2 U22.H1(SCLK)
NetR157_1: R157.1 U22.D4(LDO1ENA) U22.D5(LDO2ENA)
NetR160_2: R160.2 U22.F3(SDA)
NetR163_2: R163.2 U22.G2(~{CS}/ADDR)
NetR206_1: R206.1 U26.2(LR)
NetSB8_1: U22.F2(ADCDAT1) ; port SAI1_SDB
NetSB11_1: SW2.4 ; port PDM1_CLK1
NetSB54_2: SB54.2 U26.3(CLK) U27.3(CLK)
NetSB55_2: SB55.2 U26.4(DOUT) U27.4(DOUT)
NetSW2_1: SW2.1 U22.C6(DMICCLK)
NetSW2_5: SW2.5 U22.A9(IN2RN/DMICDAT2)
NetU22_G3: U22.G3(ADCLRCLK1/GPIO1) ; port Audio_INT

Not connected (* = marked no-connect by the designer): CN25 6(NC); CN26 6(NC); U22 A6(LINEOUTFB) A8(IN2RP/VRXP) B1(SPKOUTLN) B4(LINEOUT2P) B5(LINEOUT1P) B7(IN1RN) B8(IN2LP/VRXN) B9(IN2LN/DMICDAT1) C3(SPKOUTRN) C4(LINEOUT2N) C5(LINEOUT1N) C7(IN1RP) C8(IN1LP) E1(GPIO2/MCLK2) E5(GPIO7/ADCDAT2) F4(GPIO4/LRCLK2) F5(GPIO9/ADCDAT3) F6(GPIO11/BCLK3) F8(HPOUT2P) F9(HPOUT2N) G4(GPIO6/ADCLRCLK2) H2(GPIO3/BCLK2) H3(GPIO5/DACDAT2) H4(GPIO8/DACDAT3) H5(GPIO10/LRCLK3)

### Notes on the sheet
- Default I2C Address:0011010
- PB7
- PB6
- PE5
- PE4
- PG7
- PC2
- PE2
- To MFX
- PE6
- PE3
- MFX_GPIO5
- PC3
- PC1
- RIGHT
- (near C77) time slot0 of SAI
- (near U27) LEFT
- time slot1 of SAI
- MICBIAS1
- LEFT

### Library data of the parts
C55 C66 = Cap: Capacitor; Value: 10nF; Ordered by: Subcon
C60-C63 C69 C73 C77 = CAP: Capacitor; Value: 100nF
C64 C65 C68 C70-C72 C74 C75 C79 C80 C83 C84 C95 C96 = Cap: Capacitor; Value: 10nF
CN25 CN26 = Coupon Connectors: Header, 3-Pin, Single row
JP12 = Jumper3
R131 R151 R152 R155 R157 R160 R163 R168 R206 R207 = Res1: Resistor; Value: 1K
R145 R148 R149 R156 = Res1: Resistor; Value: 1K; Ordered by: Subcon
R147 R158 = Res1: Resistor; Ordered by: Subcon
SB54 SB55 = Circuit Breaker_close: Circuit Breaker
SW2 = MS-23D18: DPDT; Revision 1: Jul-2002: Re-released for DXP Platform.; Revision 2: 17-Dec-2003: Schematic revised, PCB Footprint replaced.
U26 U27 = MP34DT01TR: MEMS audio sensor

## Sheet ExtensionConnector.SchDoc: Extension Connectors
size A4; DocumentNumber: MB1246; Revision: B.2; SheetNumber: 14; SheetTotal: 17; Project: STM32H7x3I-EVAL
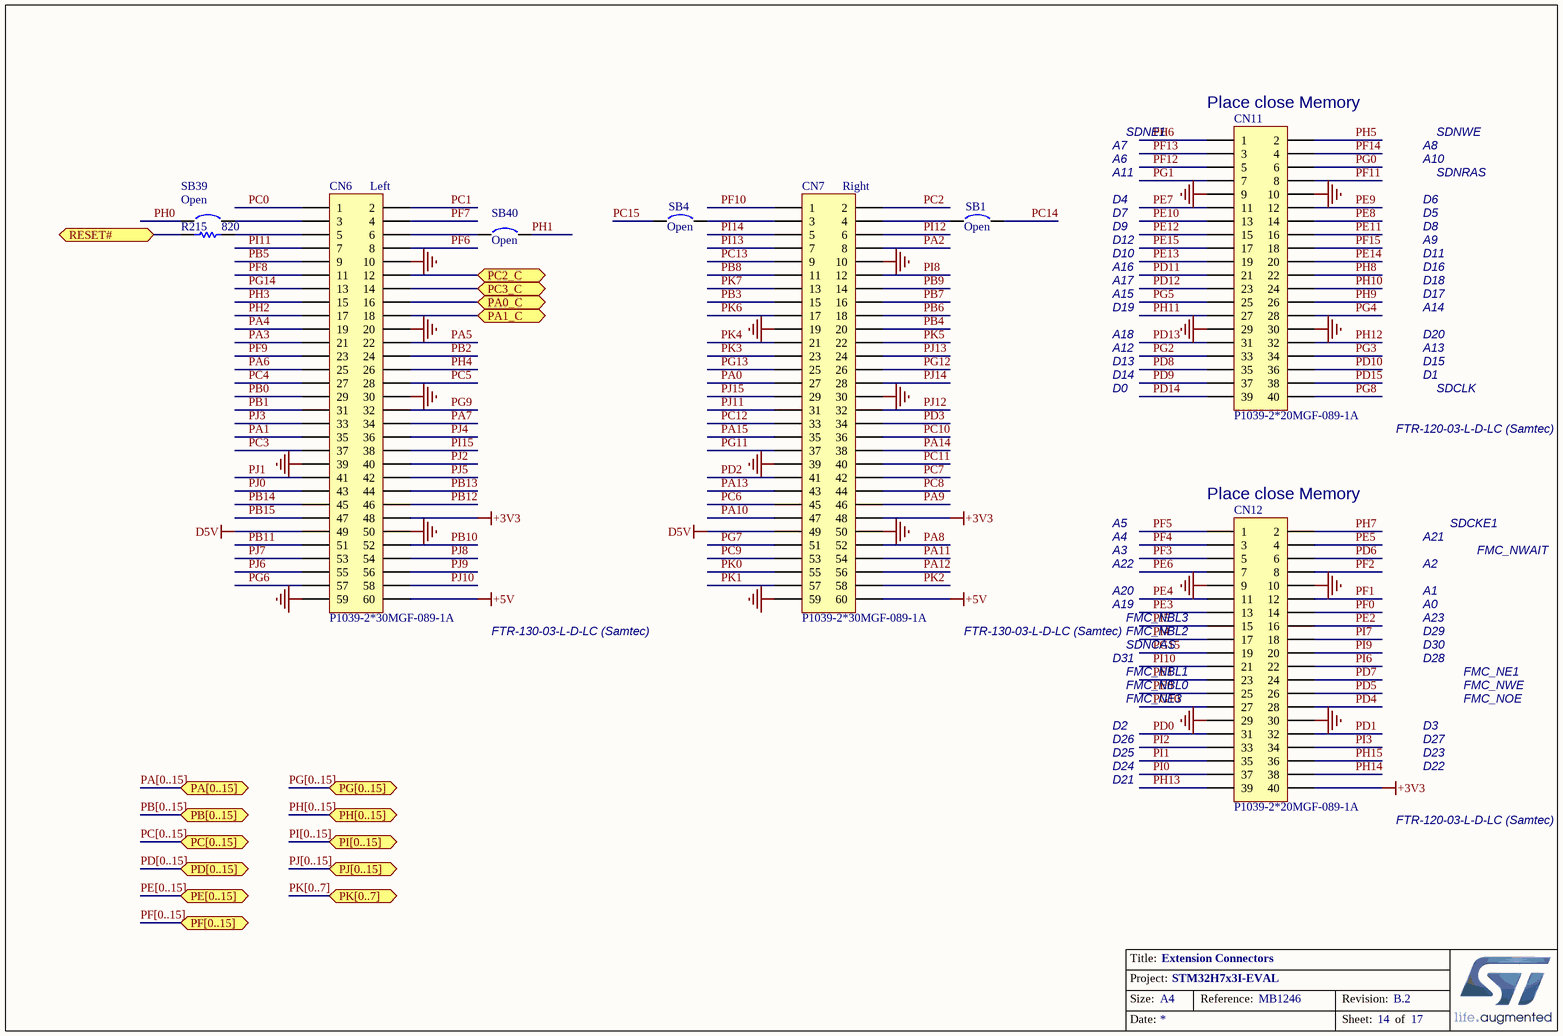
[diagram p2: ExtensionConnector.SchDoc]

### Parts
CN6  P1039-2*30MGF-089-1A  [FTR-130-53-L-D-LC]
CN7  P1039-2*30MGF-089-1A  [FTR-130-53-L-D-LC]
CN11  P1039-2*20MGF-089-1A  [FTR-120-53-L-D-LC]
CN12  P1039-2*20MGF-089-1A  [FTR-120-53-L-D-LC]
R215  820  [0603R]
SB1  Open  [0402R]
SB4  Open  [0402R]
SB39  Open  [SB_0603]
SB40  Open  [SB_0603]

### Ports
PA0_C (bidir), PA1_C (bidir), PA[0..15] (bidir), PB[0..15] (bidir), PC2_C (bidir), PC3_C (bidir), PC[0..15] (bidir), PD[0..15] (bidir), PE[0..15] (bidir), PF[0..15] (bidir), PG[0..15] (bidir), PH[0..15] (bidir), PI[0..15] (bidir), PJ[0..15] (bidir), PK[0..7] (bidir), RESET# (bidir)

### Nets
+3V3: CN6.48 CN7.48 CN12.40
+5V: CN6.60 CN7.60
D5V: CN6.49 CN7.49
GND: CN6.10 CN6.20 CN6.30 CN6.39 CN6.50 CN6.59 CN7.10 CN7.19 CN7.30 CN7.39 CN7.50 CN7.59 CN11.9 CN11.10 CN11.29 CN11.30 CN12.9 CN12.10 CN12.29 CN12.30
PA0: CN7.27
PA0_C: CN6.16 ; port PA0_C
PA1: CN6.35
PA1_C: CN6.18 ; port PA1_C
PA2: CN7.8
PA3: CN6.21
PA4: CN6.19
PA5: CN6.22
PA6: CN6.25  [project net LCD_BL_CTRL]
PA7: CN6.34
PA8: CN7.52
PA9: CN7.46
PA10: CN7.47
PA11: CN7.54
PA12: CN7.56
PA13: CN7.43
PA14: CN7.38
PA15: CN7.35
PB0: CN6.29
PB1: CN6.31
PB2: CN6.24
PB3: CN7.15
PB4: CN7.20
PB5: CN6.9
PB6: CN7.18  [project net I2C1_SCL]
PB7: CN7.16  [project net I2C1_SDA]
PB8: CN7.11
PB9: CN7.14
PB10: CN6.52
PB11: CN6.51
PB12: CN6.46
PB13: CN6.44
PB14: CN6.45
PB15: CN6.47
PC0: CN6.1
PC1: CN6.2
PC2: CN7.2
PC2_C: CN6.12 ; port PC2_C
PC3: CN6.37
PC3_C: CN6.14 ; port PC3_C
PC4: CN6.27
PC5: CN6.28
PC6: CN7.45
PC7: CN7.42
PC8: CN7.44
PC9: CN7.53
PC10: CN7.36
PC11: CN7.40
PC12: CN7.33
PC13: CN7.9
PC14: SB1.1
PC15: SB4.1
PD0: CN12.31  [project net D2]
PD1: CN12.32  [project net D3]
PD2: CN7.41
PD3: CN7.34
PD4: CN12.28
PD5: CN12.26
PD6: CN12.6
PD7: CN12.24
PD8: CN11.35  [project net D13]
PD9: CN11.37  [project net D14]
PD10: CN11.36  [project net D15]
PD11: CN11.21  [project net A16]
PD12: CN11.23  [project net A17]
PD13: CN11.31  [project net A18]
PD14: CN11.39  [project net D0]
PD15: CN11.38  [project net D1]
PE0: CN12.25
PE1: CN12.23
PE2: CN12.16  [project net A23]
PE3: CN12.13  [project net A19]
PE4: CN12.11  [project net A20]
PE5: CN12.4  [project net A21]
PE6: CN12.7  [project net A22]
PE7: CN11.11  [project net D4]
PE8: CN11.14  [project net D5]
PE9: CN11.12  [project net D6]
PE10: CN11.13  [project net D7]
PE11: CN11.16  [project net D8]
PE12: CN11.15  [project net D9]
PE13: CN11.19  [project net D10]
PE14: CN11.20  [project net D11]
PE15: CN11.17  [project net D12]
PF0: CN12.14  [project net A0]
PF1: CN12.12  [project net A1]
PF2: CN12.8  [project net A2]
PF3: CN12.5  [project net A3]
PF4: CN12.3  [project net A4]
PF5: CN12.1  [project net A5]
PF6: CN6.8
PF7: CN6.4
PF8: CN6.11
PF9: CN6.23
PF10: CN7.1
PF11: CN11.8
PF12: CN11.5  [project net A6]
PF13: CN11.3  [project net A7]
PF14: CN11.4  [project net A8]
PF15: CN11.18  [project net A9]
PG0: CN11.6  [project net A10]
PG1: CN11.7  [project net A11]
PG2: CN11.33  [project net A12]
PG3: CN11.34  [project net A13]
PG4: CN11.28  [project net A14]
PG5: CN11.25  [project net A15]
PG6: CN6.57
PG7: CN7.51
PG8: CN11.40
PG9: CN6.32  [project net BK2_IO2]
PG10: CN12.27
PG11: CN7.37
PG12: CN7.26
PG13: CN7.25
PG14: CN6.13  [project net BK2_IO3]
PG15: CN12.19
PH0: SB39.1
PH1: SB40.1
PH2: CN6.17  [project net BK2_IO0]
PH3: CN6.15  [project net BK2_IO1]
PH4: CN6.26
PH5: CN11.2
PH6: CN11.1
PH7: CN12.2
PH8: CN11.22  [project net D16]
PH9: CN11.26  [project net D17]
PH10: CN11.24  [project net D18]
PH11: CN11.27  [project net D19]
PH12: CN11.32  [project net D20]
PH13: CN12.39  [project net D21]
PH14: CN12.38  [project net D22]
PH15: CN12.36  [project net D23]
PI0: CN12.37  [project net D24]
PI1: CN12.35  [project net D25]
PI2: CN12.33  [project net D26]
PI3: CN12.34  [project net D27]
PI4: CN12.17
PI5: CN12.15
PI6: CN12.22  [project net D28]
PI7: CN12.18  [project net D29]
PI8: CN7.12
PI9: CN12.20  [project net D30]
PI10: CN12.21  [project net D31]
PI11: CN6.7
PI12: CN7.6
PI13: CN7.7
PI14: CN7.5
PI15: CN6.38  [project net LCD_R0]
PJ0: CN6.43  [project net LCD_R1]
PJ1: CN6.41  [project net LCD_R2]
PJ2: CN6.40  [project net LCD_R3]
PJ3: CN6.33  [project net LCD_R4]
PJ4: CN6.36  [project net LCD_R5]
PJ5: CN6.42  [project net LCD_R6]
PJ6: CN6.55  [project net LCD_R7]
PJ7: CN6.53  [project net LCD_G0]
PJ8: CN6.54  [project net LCD_G1]
PJ9: CN6.56  [project net LCD_G2]
PJ10: CN6.58  [project net LCD_G3]
PJ11: CN7.31  [project net LCD_G4]
PJ12: CN7.32  [project net LCD_B0]
PJ13: CN7.24  [project net LCD_B1]
PJ14: CN7.28  [project net LCD_B2]
PJ15: CN7.29  [project net LCD_B3]
PK0: CN7.55  [project net LCD_G5]
PK1: CN7.57  [project net LCD_G6]
PK2: CN7.58  [project net LCD_G7]
PK3: CN7.23  [project net LCD_B4]
PK4: CN7.21  [project net LCD_B5]
PK5: CN7.22  [project net LCD_B6]
PK6: CN7.17  [project net LCD_B7]
PK7: CN7.13
RESET#: R215.1 ; port RESET#
NetCN6_3: CN6.3 SB39.2
NetCN6_5: CN6.5 R215.2
NetCN6_6: CN6.6 SB40.2
NetCN7_3: CN7.3 SB4.2
NetCN7_4: CN7.4 SB1.2

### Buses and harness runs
bus PA[0..15] = port PA[0..15]
bus PB[0..15] = port PB[0..15]
bus PC[0..15] = port PC[0..15]
bus PD[0..15] = port PD[0..15]
bus PE[0..15] = port PE[0..15]
bus PF[0..15] = port PF[0..15]
bus PG[0..15] = port PG[0..15]
bus PH[0..15] = port PH[0..15]
bus PI[0..15] = port PI[0..15]
bus PJ[0..15] = port PJ[0..15]
bus PK[0..7] = port PK[0..7]

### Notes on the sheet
- (near CN11) Place close Memory
- A6
- A7
- A11
- SDNE1
- A8
- A10
- SDNRAS
- SDNWE
- (near CN6) Left
- (near CN7) Right
- D4
- D7
- D9
- D12
- D5
- D6
- D8
- A9
- A16
- A17
- D10
- A15
- D19
- D11
- A14
- D16
- D17
- D18
- D13
- D14
- A18
- A12
- D15
- D1
- A13
- D20
- D0
- (near CN11) FTR-120-03-L-D-LC (Samtec)
- SDCLK
- (near CN12) Place close Memory
- A22
- A3
- A4
- A5
- A21
- A2
- SDCKE1
- FMC_NWAIT
- (near CN6) FTR-130-03-L-D-LC (Samtec)
- (near CN7) FTR-130-03-L-D-LC (Samtec)
- A19
- A20
- SDNCAS
- FMC_NBL2
- FMC_NBL3
- A23
- A0
- A1
- D29
- D30
- D31
- FMC_NBL0
- FMC_NBL1
- FMC_NE3
- D28
- FMC_NOE
- FMC_NWE
- FMC_NE1
- D2
- D21
- D24
- D25
- D26
- D3
- D22
- D23
- D27
- (near CN12) FTR-120-03-L-D-LC (Samtec)

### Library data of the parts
CN6 CN7 = FTR-130-53-L-D-LC: Header, 40-Pin, Dual row
CN11 CN12 = FTR-120-53-L-D-LC: Header, 20-Pin, Dual row
R215 = res1: Resistor; Value: 1K
SB1 SB4 SB39 SB40 = Circuit Breaker

## Sheet FDCAN&QSPI.SchDoc: FDCAN & QSPI
size A4; DocumentNumber: MB1246; Revision: B.2; SheetNumber: 11; SheetTotal: 17; Project: STM32H7x3I-EVAL
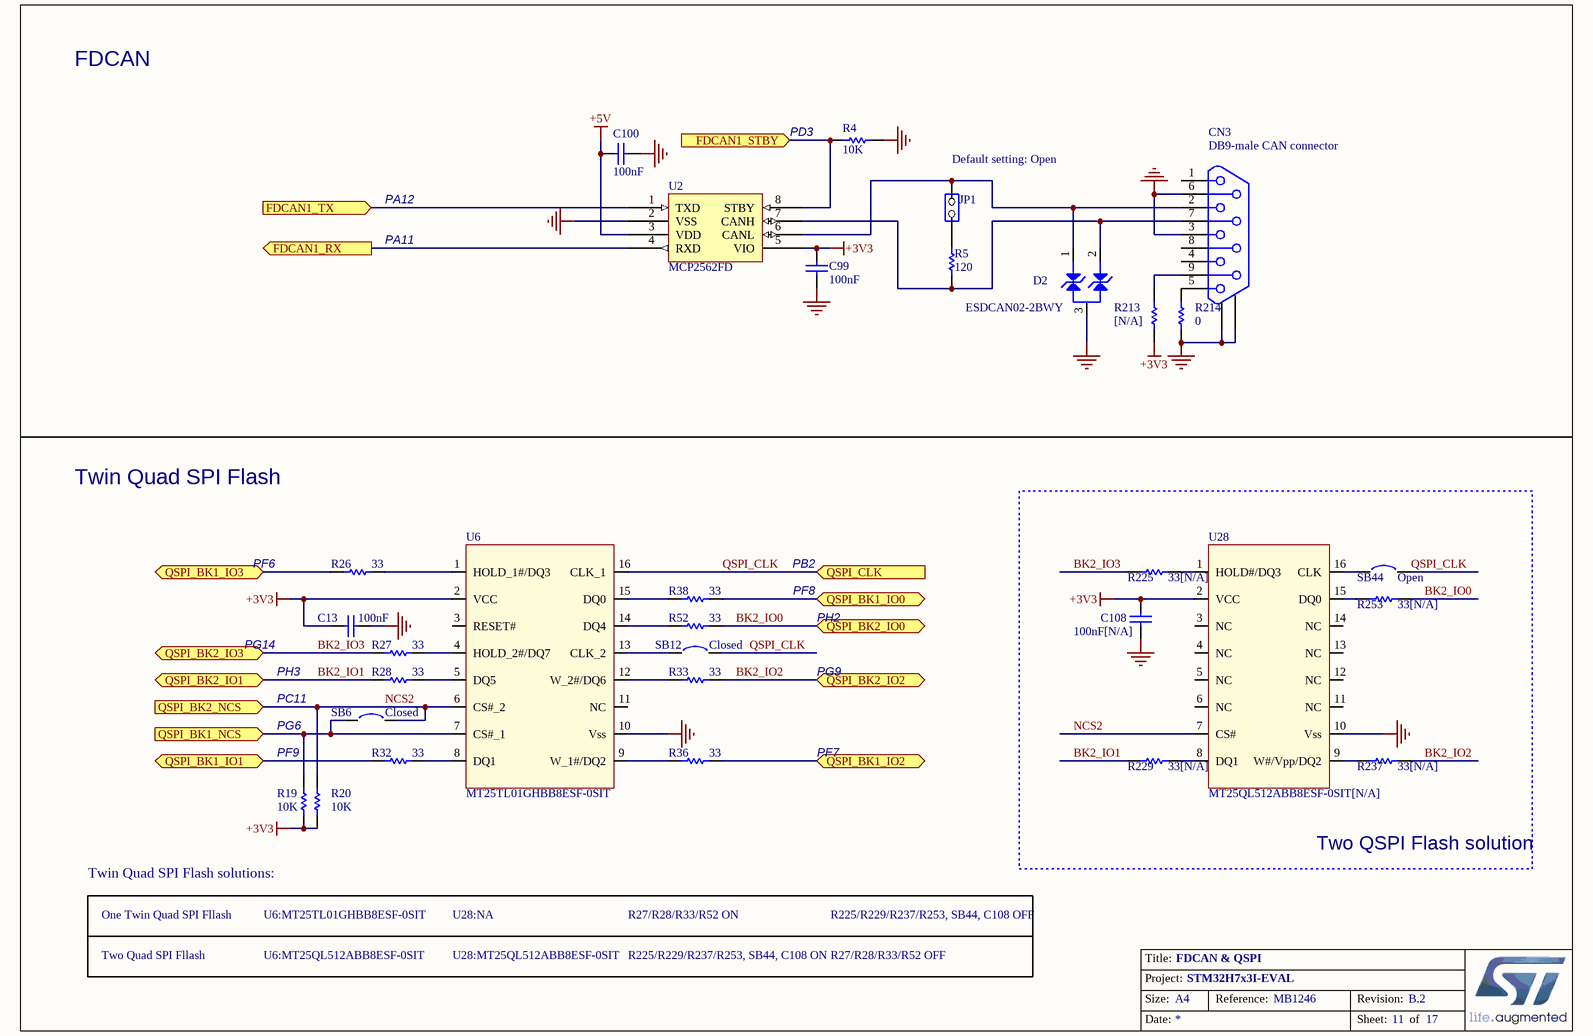
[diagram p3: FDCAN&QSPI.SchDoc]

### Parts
C13  100nF  [0402C]
C99  100nF  [0603C]
C100  100nF  [0603C]
C108  100nF[N/A]  [0402C]
CN3  DB9-male CAN connector  [DB9/M]
D2  ESDCAN02-2BWY  [SOT-323]
JP1  (no value)  [SIP2]
R4  10K  [0603R]
R5  120  [0603R]
R19  10K  [0402R]
R20  10K  [0402R]
R26  33  [0603R]
R27  33  [0603R]
R28  33  [0603R]
R32  33  [0603R]
R33  33  [0603R]
R36  33  [0603R]
R38  33  [0603R]
R52  33  [0603R]
R213  [N/A]  [0603R]
R214  0  [0603R]
R225  33[N/A]  [0603R]
R229  33[N/A]  [0603R]
R237  33[N/A]  [0603R]
R253  33[N/A]  [0603R]
SB6  Closed  [SB_0603]
SB12  Closed  [SB_0603]
SB44  Open  [SB_0603]
U2  MCP2562FD  [SOIC8_1R27_4R9X6]
U6  MT25TL01GHBB8ESF-0SIT  [SOIC16W_1R27_10R3X10R33]
U28  MT25QL512ABB8ESF-0SIT[N/A]  [SOIC16W_1R27_10R3X10R33]

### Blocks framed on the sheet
Two QSPI Flash solution: C108 R225 R229 R237 R253 SB44 U28

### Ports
FDCAN1_RX (out), FDCAN1_STBY (in), FDCAN1_TX (in), QSPI_BK1_IO0 (bidir), QSPI_BK1_IO1 (bidir), QSPI_BK1_IO2 (bidir), QSPI_BK1_IO3 (bidir), QSPI_BK1_NCS (in), QSPI_BK2_IO0 (bidir), QSPI_BK2_IO1 (bidir), QSPI_BK2_IO2 (bidir), QSPI_BK2_IO3 (bidir), QSPI_BK2_NCS (in), QSPI_CLK (in)

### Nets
+3V3: C13.1 C99.1 C108.1 R19.2 R20.2 R213.1 U2.5(VIO) U6.2(VCC) U28.2(VCC)
+5V: C100.1 U2.3(VDD)
GND: C13.2 C99.2 C100.2 C108.2 CN3.3 CN3.6 CN3.10 CN3.11 D2.3 R4.2 R214.1 U2.2(VSS) U6.10(Vss) U28.10(Vss)
BK2_IO0: R52.1 R253.1 ; port QSPI_BK2_IO0
BK2_IO1: R28.2 R229.2 ; port QSPI_BK2_IO1
BK2_IO2: R33.1 R237.1 ; port QSPI_BK2_IO2
BK2_IO3: R27.2 R225.2 ; port QSPI_BK2_IO3
NCS2: R20.1 SB6.2 U6.6(CS#_2) U28.7(CS#) ; port QSPI_BK2_NCS
PD3: R4.1 U2.8(STBY) ; port FDCAN1_STBY
PF6: R26.2 ; port QSPI_BK1_IO3
PF7: R36.1 ; port QSPI_BK1_IO2
PF8: R38.1 ; port QSPI_BK1_IO0
PF9: R32.2 ; port QSPI_BK1_IO1
PG6: R19.1 SB6.1 U6.7(CS#_1) ; port QSPI_BK1_NCS
QSPI_CLK: SB12.2 SB44.2 U6.16(CLK_1) ; port QSPI_CLK  [project net PB2]
NetCN3_2: CN3.2 D2.1 JP1.2(NO) U2.6(CANL)
NetCN3_5: CN3.5 R214.2
NetCN3_7: CN3.7 D2.2 R5.1 U2.7(CANH)
NetCN3_9: CN3.9 R213.2
NetJP1_1: JP1.1(COMMON) R5.2
NetJP2_2: U2.1(TXD) ; port FDCAN1_TX
NetR26_1: R26.1 U6.1(HOLD_1#/DQ3)
NetR27_1: R27.1 U6.4(HOLD_2#/DQ7)
NetR28_1: R28.1 U6.5(DQ5)
NetR32_1: R32.1 U6.8(DQ1)
NetR33_2: R33.2 U6.12(W_2#/DQ6)
NetR36_2: R36.2 U6.9(W_1#/DQ2)
NetR38_2: R38.2 U6.15(DQ0)
NetR52_2: R52.2 U6.14(DQ4)
NetR225_1: R225.1 U28.1(HOLD#/DQ3)
NetR229_1: R229.1 U28.8(DQ1)
NetR237_2: R237.2 U28.9(W#/Vpp/DQ2)
NetR253_2: R253.2 U28.15(DQ0)
NetSB12_1: SB12.1 U6.13(CLK_2)
NetSB44_1: SB44.1 U28.16(CLK)
NetSB50_1: U2.4(RXD) ; port FDCAN1_RX

Not connected (* = marked no-connect by the designer): CN3 1 4 8; U6 3(RESET#) 11(NC); U28 3(NC) 4(NC) 5(NC) 6(NC) 11(NC) 12(NC) 13(NC) 14(NC)

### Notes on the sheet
- FDCAN
- (near R4) PD3
- (near JP1) Default setting: Open
- PA12
- PA11
- Twin Quad SPI Flash
- PF6
- PB2
- (near C13) PG14
- PF8
- PH2
- PH3
- PC11
- PG9
- PF9
- PG6
- PF7
- Twin Quad SPI Flash solutions:
- One Twin Quad SPI Fllash
- U6:MT25TL01GHBB8ESF-0SIT
- U28:NA
- R27/R28/R33/R52 ON
- R225/R229/R237/R253, SB44, C108 OFF
- Two Quad SPI Fllash
- U6:MT25QL512ABB8ESF-0SIT
- U28:MT25QL512ABB8ESF-0SIT
- R225/R229/R237/R253, SB44, C108 ON
- R27/R28/R33/R52 OFF

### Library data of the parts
C13 C108 = Cap: as C55 on sheet Audio
C99 C100 = Cap: Capacitor; Value: 10nF
CN3 = DB9-CAN
JP1 = JP2
R4 R26-R28 R32 R33 R36 R38 R52 R225 R229 R237 R253 = Res1: Resistor; Value: 1K
R5 R213 R214 = res1: Resistor; Value: 1K
R19 R20 = res1: Resistor; Value: 1K; Ordered by: Subcon
SB6 SB12 = Circuit Breaker_close: Circuit Breaker
SB44 = Circuit Breaker
U2 = MCP2562FD: CAN Flexible Data Rate Transceiver
U6 = MT25TL01GHBA8ESF-0SIT: Serial NOR Flash Memory; ECCN_US/EU: 3A991
U28 = QSPI_16pins: ECCN_US/EU: 3A991

## Sheet Memory.SchDoc: SRAM & FLASH & SDRAM
size A4; DocumentNumber: MB1246; Revision: B.2; SheetNumber: 4; SheetTotal: 17; Project: STM32H7x3I-EVAL
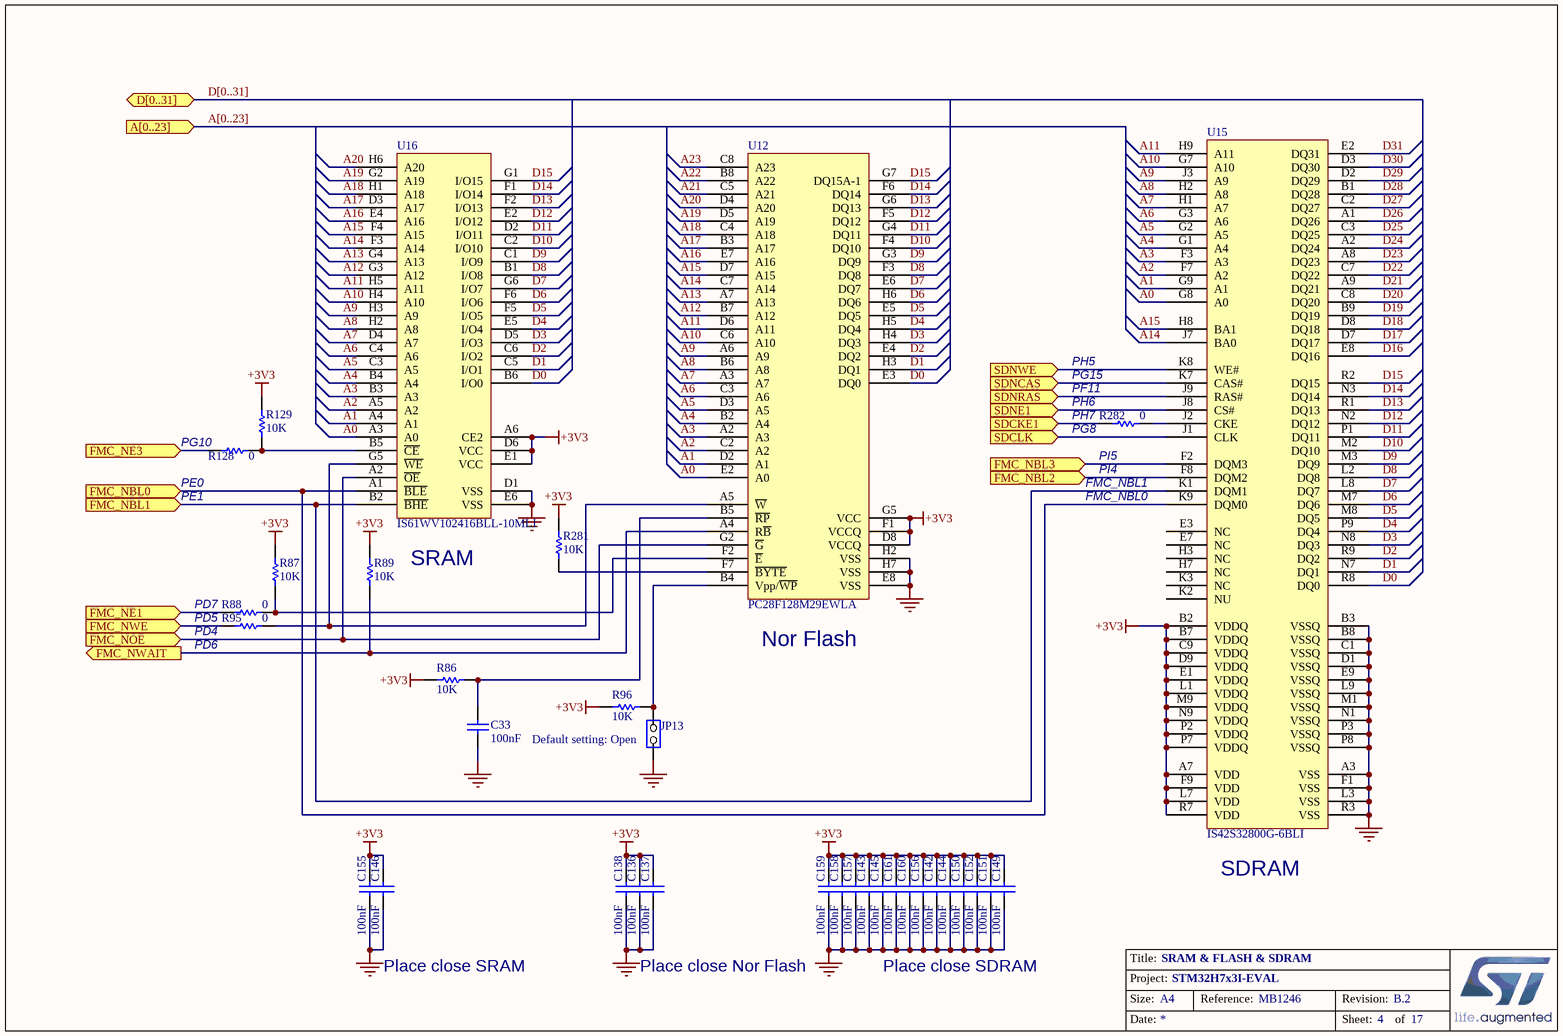
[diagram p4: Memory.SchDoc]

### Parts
C33  100nF  [0603C]
C136  100nF  [0603C]
C137  100nF  [0603C]
C138  100nF  [0603C]
C142  100nF  [0603C]
C143  100nF  [0603C]
C144  100nF  [0603C]
C145  100nF  [0603C]
C146  100nF  [0603C]
C149  100nF  [0603C]
C150  100nF  [0603C]
C151  100nF  [0603C]
C152  100nF  [0603C]
C155  100nF  [0603C]
C156  100nF  [0603C]
C157  100nF  [0603C]
C158  100nF  [0603C]
C159  100nF  [0603C]
C160  100nF  [0603C]
C161  100nF  [0603C]
JP13  (no value)  [SIP2]
R86  10K  [0603R]
R87  10K  [0603R]
R88  0  [0603R]
R89  10K  [0603R]
R95  0  [0603R]
R96  10K  [0603R]
R128  0  [0603R]
R129  10K  [0603R]
R281  10K  [0603R]
R282  0  [0603R]
U12  PC28F128M29EWLA  [FBGA64_1_11X13]
U15  IS42S32800G-6BLI  [FBGA90_0R8_8X13]
U16  IS61WV102416BLL-10MLI  [BGA48_0R75_9X11]

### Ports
A[0..23] (in), D[0..31] (bidir), FMC_NBL0 (in), FMC_NBL1 (in), FMC_NBL2 (in), FMC_NBL3 (in), FMC_NE1 (in), FMC_NE3 (in), FMC_NOE (in), FMC_NWAIT (out), FMC_NWE (in), SDCKE1 (in), SDCLK (in), SDNCAS (in), SDNE1 (in), SDNRAS (in), SDNWE (in)

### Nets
+3V3: C136.1 C137.1 C138.1 C142.1 C143.1 C144.1 C145.1 C146.1 C149.1 C150.1 C151.1 C152.1 C155.1 C156.1 C157.1 C158.1 C159.1 C160.1 C161.1 R86.1 R87.2 R89.2 R96.2 R129.2 R281.2 U12.D8(VCCQ) U12.F1(VCCQ) U12.G5(VCC) U15.A7(VDD) U15.B2(VDDQ) U15.B7(VDDQ) U15.C9(VDDQ) U15.D9(VDDQ) U15.E1(VDDQ) U15.F9(VDD) U15.L1(VDDQ) U15.L7(VDD) U15.M9(VDDQ) U15.N9(VDDQ) U15.P2(VDDQ) U15.P7(VDDQ) U15.R7(VDD) U16.A6(CE2) U16.D6(VCC) U16.E1(VCC)
GND: C33.2 C136.2 C137.2 C138.2 C142.2 C143.2 C144.2 C145.2 C146.2 C149.2 C150.2 C151.2 C152.2 C155.2 C156.2 C157.2 C158.2 C159.2 C160.2 C161.2 JP13.1(COMMON) U12.E8(VSS) U12.H2(VSS) U12.H7(VSS) U15.A3(VSS) U15.B3(VSSQ) U15.B8(VSSQ) U15.C1(VSSQ) U15.D1(VSSQ) U15.E9(VSSQ) U15.F1(VSS) U15.L3(VSS) U15.L9(VSSQ) U15.M1(VSSQ) U15.N1(VSSQ) U15.P3(VSSQ) U15.P8(VSSQ) U15.R3(VSS) U16.D1(VSS) U16.E6(VSS)
A0: U12.E2(A0) U15.G8(A0) U16.A3(A0)
A1: U12.D2(A1) U15.G9(A1) U16.A4(A1)
A2: U12.C2(A2) U15.F7(A2) U16.A5(A2)
A3: U12.A2(A3) U15.F3(A3) U16.B3(A3)
A4: U12.B2(A4) U15.G1(A4) U16.B4(A4)
A5: U12.D3(A5) U15.G2(A5) U16.C3(A5)
A6: U12.C3(A6) U15.G3(A6) U16.C4(A6)
A7: U12.A3(A7) U15.H1(A7) U16.D4(A7)
A8: U12.B6(A8) U15.H2(A8) U16.H2(A8)
A9: U12.A6(A9) U15.J3(A9) U16.H3(A9)
A10: U12.C6(A10) U15.G7(A10) U16.H4(A10)
A11: U12.D6(A11) U15.H9(A11) U16.H5(A11)
A12: U12.B7(A12) U16.G3(A12)
A13: U12.A7(A13) U16.G4(A13)
A14: U12.C7(A14) U15.J7(BA0) U16.F3(A14)
A15: U12.D7(A15) U15.H8(BA1) U16.F4(A15)
A16: U12.E7(A16) U16.E4(A16)
A17: U12.B3(A17) U16.D3(A17)
A18: U12.C4(A18) U16.H1(A18)
A19: U12.D5(A19) U16.G2(A19)
A20: U12.D4(A20) U16.H6(A20)
A21: U12.C5(A21)
A22: U12.B8(A22)
A23: U12.C8(A23)
D0: U12.E3(DQ0) U15.R8(DQ0) U16.B6(I/O0)
D1: U12.H3(DQ1) U15.N7(DQ1) U16.C5(I/O1)
D2: U12.E4(DQ2) U15.R9(DQ2) U16.C6(I/O2)
D3: U12.H4(DQ3) U15.N8(DQ3) U16.D5(I/O3)
D4: U12.H5(DQ4) U15.P9(DQ4) U16.E5(I/O4)
D5: U12.E5(DQ5) U15.M8(DQ5) U16.F5(I/O5)
D6: U12.H6(DQ6) U15.M7(DQ6) U16.F6(I/O6)
D7: U12.E6(DQ7) U15.L8(DQ7) U16.G6(I/O7)
D8: U12.F3(DQ8) U15.L2(DQ8) U16.B1(I/O8)
D9: U12.G3(DQ9) U15.M3(DQ9) U16.C1(I/O9)
D10: U12.F4(DQ10) U15.M2(DQ10) U16.C2(I/O10)
D11: U12.G4(DQ11) U15.P1(DQ11) U16.D2(I/O11)
D12: U12.F5(DQ12) U15.N2(DQ12) U16.E2(I/O12)
D13: U12.G6(DQ13) U15.R1(DQ13) U16.F2(I/O13)
D14: U12.F6(DQ14) U15.N3(DQ14) U16.F1(I/O14)
D15: U12.G7(DQ15A-1) U15.R2(DQ15) U16.G1(I/O15)
D16: U15.E8(DQ16)
D17: U15.D7(DQ17)
D18: U15.D8(DQ18)
D19: U15.B9(DQ19)
D20: U15.C8(DQ20)
D21: U15.A9(DQ21)
D22: U15.C7(DQ22)
D23: U15.A8(DQ23)
D24: U15.A2(DQ24)
D25: U15.C3(DQ25)
D26: U15.A1(DQ26)
D27: U15.C2(DQ27)
D28: U15.B1(DQ28)
D29: U15.D2(DQ29)
D30: U15.D3(DQ30)
D31: U15.E2(DQ31)
PD4: U12.G2(~{G}) U16.A2(~{OE}) ; port FMC_NOE
PD5: R95.2 ; port FMC_NWE
PD6: R89.1 U12.A4(R~{B}) ; port FMC_NWAIT
PD7: R88.2 ; port FMC_NE1
PE0: U15.K9(DQM0) U16.A1(~{BLE}) ; port FMC_NBL0
PE1: U15.K1(DQM1) U16.B2(~{BHE}) ; port FMC_NBL1
PF11: U15.J9(RAS#) ; port SDNRAS
PG8: U15.J1(CLK) ; port SDCLK
PG10: R128.2 ; port FMC_NE3
PG15: U15.K7(CAS#) ; port SDNCAS
PH5: U15.K8(WE#) ; port SDNWE
PH6: U15.J8(CS#) ; port SDNE1
PH7: R282.2 ; port SDCKE1
PI4: U15.F8(DQM2) ; port FMC_NBL2
PI5: U15.F2(DQM3) ; port FMC_NBL3
NetC33_1: C33.1 R86.2 U12.B5(~{RP})
NetJP13_2: JP13.2(NO) R96.1 U12.B4(Vpp/~{WP})
NetR87_1: R87.1 R88.1 U12.F2(~{E})
NetR95_1: R95.1 U12.A5(~{W}) U16.G5(~{WE})
NetR128_1: R128.1 R129.1 U16.B5(~{CE})
NetR281_1: R281.1 U12.F7(~{BYTE})
NetR282_1: R282.1 U15.J2(CKE)

Not connected (* = marked no-connect by the designer): U15 E3(NC) E7(NC) H3(NC) H7(NC) K2(NU) K3(NC)

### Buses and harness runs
bus A[0..23] = port A[0..23]
bus D[0..31] = port D[0..31]

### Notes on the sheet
- PH5
- (near R282) PG15
- (near R128) PG10
- (near R282) PF11
- (near R282) PH6
- (near R282) PH7
- (near R282) PG8
- (near R128) PE1
- (near R128) PE0
- FMC_NBL1
- FMC_NBL0
- (near R282) PI5
- (near R282) PI4
- SRAM
- PD5
- PD7
- PD6
- PD4
- (near U12) Nor Flash
- (near JP13) Default setting: Open
- (near U15) SDRAM
- Place close SRAM
- Place close Nor Flash
- Place close SDRAM

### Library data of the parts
C33 C136-C138 C142-C146 C149-C152 C155-C161 = Cap: Capacitor; Value: 10nF
JP13 = JP2
R86-R89 R95 R96 R128 R129 R281 R282 = Res1: Resistor; Value: 1K
U12 = M29W128FL70ZA6E
U15 = MT48LC4M32B2B5

## Sheet MFX.SchDoc: MFX
size A4; DocumentNumber: MB1246; Revision: B.2; SheetNumber: 16; SheetTotal: 17; Project: STM32H7x3I-EVAL
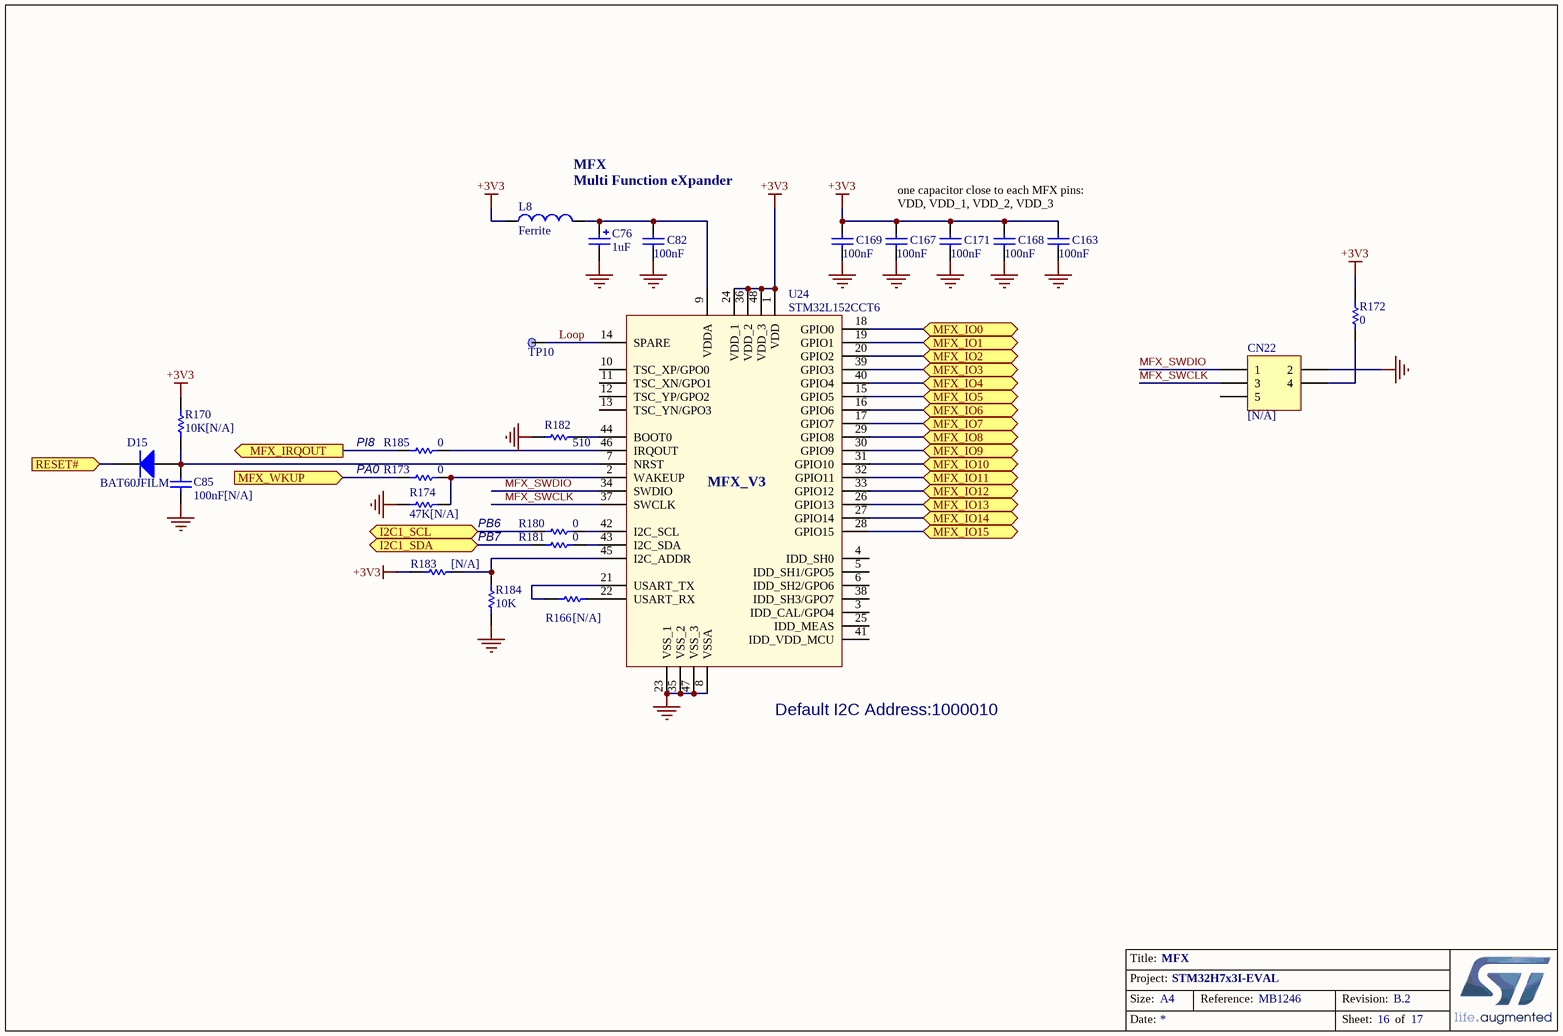
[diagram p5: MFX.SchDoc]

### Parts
C76  1uF  [TAN-A]
C82  100nF  [0402C]
C85  100nF[N/A]  [0402C]
C163  100nF  [0402C]
C167  100nF  [0402C]
C168  100nF  [0402C]
C169  100nF  [0402C]
C171  100nF  [0402C]
CN22  [N/A]  [HDR_2X3-1_2R54-6]
D15  BAT60JFILM  [SOD-323]
L8  Ferrite  [0603L]
R166  [N/A]  [0603R]
R170  10K[N/A]  [0402R]
R172  0  [0603R]
R173  0  [0603R]
R174  47K[N/A]  [0402R]
R180  0  [0603R]
R181  0  [0603R]
R182  510  [0402R]
R183  [N/A]  [0603R]
R184  10K  [0402R]
R185  0  [0603R]
TP10  (no value)  [TP]
U24  STM32L152CCT6  [LQFP48_0R5_9X9]

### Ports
I2C1_SCL (bidir), I2C1_SDA (bidir), MFX_IO0 (bidir), MFX_IO1 (bidir), MFX_IO2 (bidir), MFX_IO3 (bidir), MFX_IO4 (bidir), MFX_IO5 (bidir), MFX_IO6 (bidir), MFX_IO7 (bidir), MFX_IO8 (bidir), MFX_IO9 (bidir), MFX_IO10 (bidir), MFX_IO11 (bidir), MFX_IO12 (bidir), MFX_IO13 (bidir), MFX_IO14 (bidir), MFX_IO15 (bidir), MFX_IRQOUT (out), MFX_WKUP (in), RESET# (in)

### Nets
+3V3: C163.2 C167.2 C168.2 C169.2 C171.1 L8.1 R170.2 R172.1 R183.2 U24.1(VDD) U24.24(VDD_1) U24.36(VDD_2) U24.48(VDD_3)
GND: C76.2 C82.1 C85.1 C163.1 C167.1 C168.1 C169.1 C171.2 CN22.2 R174.1 R182.2 R184.2 U24.8(VSSA) U24.23(VSS_1) U24.35(VSS_2) U24.47(VSS_3)
I2C1_SCL: R180.1 ; port I2C1_SCL
I2C1_SDA: R181.1 ; port I2C1_SDA
Loop: TP10.1 U24.14(SPARE)
MFX_SWCLK: CN22.3 U24.37(SWCLK)
MFX_SWDIO: CN22.1 U24.34(SWDIO)
PA0: R173.2 ; port MFX_WKUP
PI8: R185.1 ; port MFX_IRQOUT
RESET#: D15.2(K) ; port RESET#
TOUCH_INT: U24.27(GPIO14) ; port MFX_IO14
NetB4_1: U24.20(GPIO2) ; port MFX_IO2
NetB4_2: U24.18(GPIO0) ; port MFX_IO0
NetB4_3: U24.19(GPIO1) ; port MFX_IO1
NetB4_4: U24.39(GPIO3) ; port MFX_IO3
NetB4_6: U24.40(GPIO4) ; port MFX_IO4
NetC76_1: C76.1 C82.2 L8.2 U24.9(VDDA)
NetC85_2: C85.2 D15.1(A) R170.1 U24.7(NRST)
NetCN13_10: U24.28(GPIO15) ; port MFX_IO15
NetCN22_4: CN22.4 R172.2
NetM1_1: U24.26(GPIO13) ; port MFX_IO13
NetR126_1: U24.29(GPIO8) ; port MFX_IO8
NetR141_2: U24.17(GPIO7) ; port MFX_IO7
NetR146_1: U24.16(GPIO6) ; port MFX_IO6
NetR166_1: R166.1 U24.21(USART_TX)
NetR166_2: R166.2 U24.22(USART_RX)
NetR173_1: R173.1 R174.2 U24.2(WAKEUP)
NetR180_2: R180.2 U24.42(I2C_SCL)
NetR181_2: R181.2 U24.43(I2C_SDA)
NetR182_1: R182.1 U24.44(BOOT0)
NetR183_1: R183.1 R184.1 U24.45(I2C_ADDR)
NetR185_2: R185.2 U24.46(IRQOUT)
NetR295_1: U24.31(GPIO10) ; port MFX_IO10
NetR297_1: U24.32(GPIO11) ; port MFX_IO11
NetSB29_1: U24.30(GPIO9) ; port MFX_IO9
NetSB61_1: U24.33(GPIO12) ; port MFX_IO12
NetU22_G3: U24.15(GPIO5) ; port MFX_IO5

Not connected (* = marked no-connect by the designer): CN22 5; U24 3(IDD_CAL/GPO4) 4(IDD_SH0) 5(IDD_SH1/GPO5) 6(IDD_SH2/GPO6) 10(TSC_XP/GPO0) 11(TSC_XN/GPO1) 12(TSC_YP/GPO2) 13(TSC_YN/GPO3) 25(IDD_MEAS) 38(IDD_SH3/GPO7) 41(IDD_VDD_MCU)

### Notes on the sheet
- MFX
  Multi Function eXpander
- one capacitor close to each MFX pins: VDD, VDD_1, VDD_2, VDD_3
- PI8
- PA0
- PB6
- PB7
- (near U24) Default I2C Address:1000010

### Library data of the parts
C76 = Cap_1uF_POL_10%_TANA: Polarized Capacitor,1uF,16V,10%,typeA,AVX; Manuf_Part_1: TAJA105K016R
C82 C85 C163 C167-C169 C171 = Cap_100nF_X7R_10%_0402: Capacitor,100nF,16V,X7R,10%,0402,YAGEO; Manuf_Part_1: CC0402KRX7R7BB104
CN22 = Header 3X2: Header, 3-Pin, Dual row
D15 = Diode: Default Diode; Code - JEDEC: DO-214-AB
L8 = BEAD_600R_350MA_0603: Bead,600R,350mA,0603,FCM1608KF-601T03,Tai-tech; Manuf_2: TDK; Manuf_Part_2: MPZ1608S300A; Value: 100uH; Comment_1: bead,30R,5A,0603,MPZ1608S300A,TDK
R166 = res1: Resistor; Value: 1K; Ordered by: Subcon
R170 R174 R182 = Resistor_ST: Resistor 0402 / 0603 / 0805; Description: Resistor 0402 or 0603 or 0805; Value: 10K
R172 R180 R181 R185 = Res1: Resistor; Value: 1K; Ordered by: Subcon
R173 R183 = Res1: Resistor; Value: 1K
R184 = Resistor_ST: Resistor 0402 / 0603 / 0805; Description: Resistor 0402 or 0603 or 0805
TP10 = TP
U24 = MFX: Multifunction expander

## Sheet Power.SchDoc: Power
size A4; DocumentNumber: MB1246; Revision: B.2; SheetNumber: 3; SheetTotal: 17; Project: STM32H7x3I-EVAL
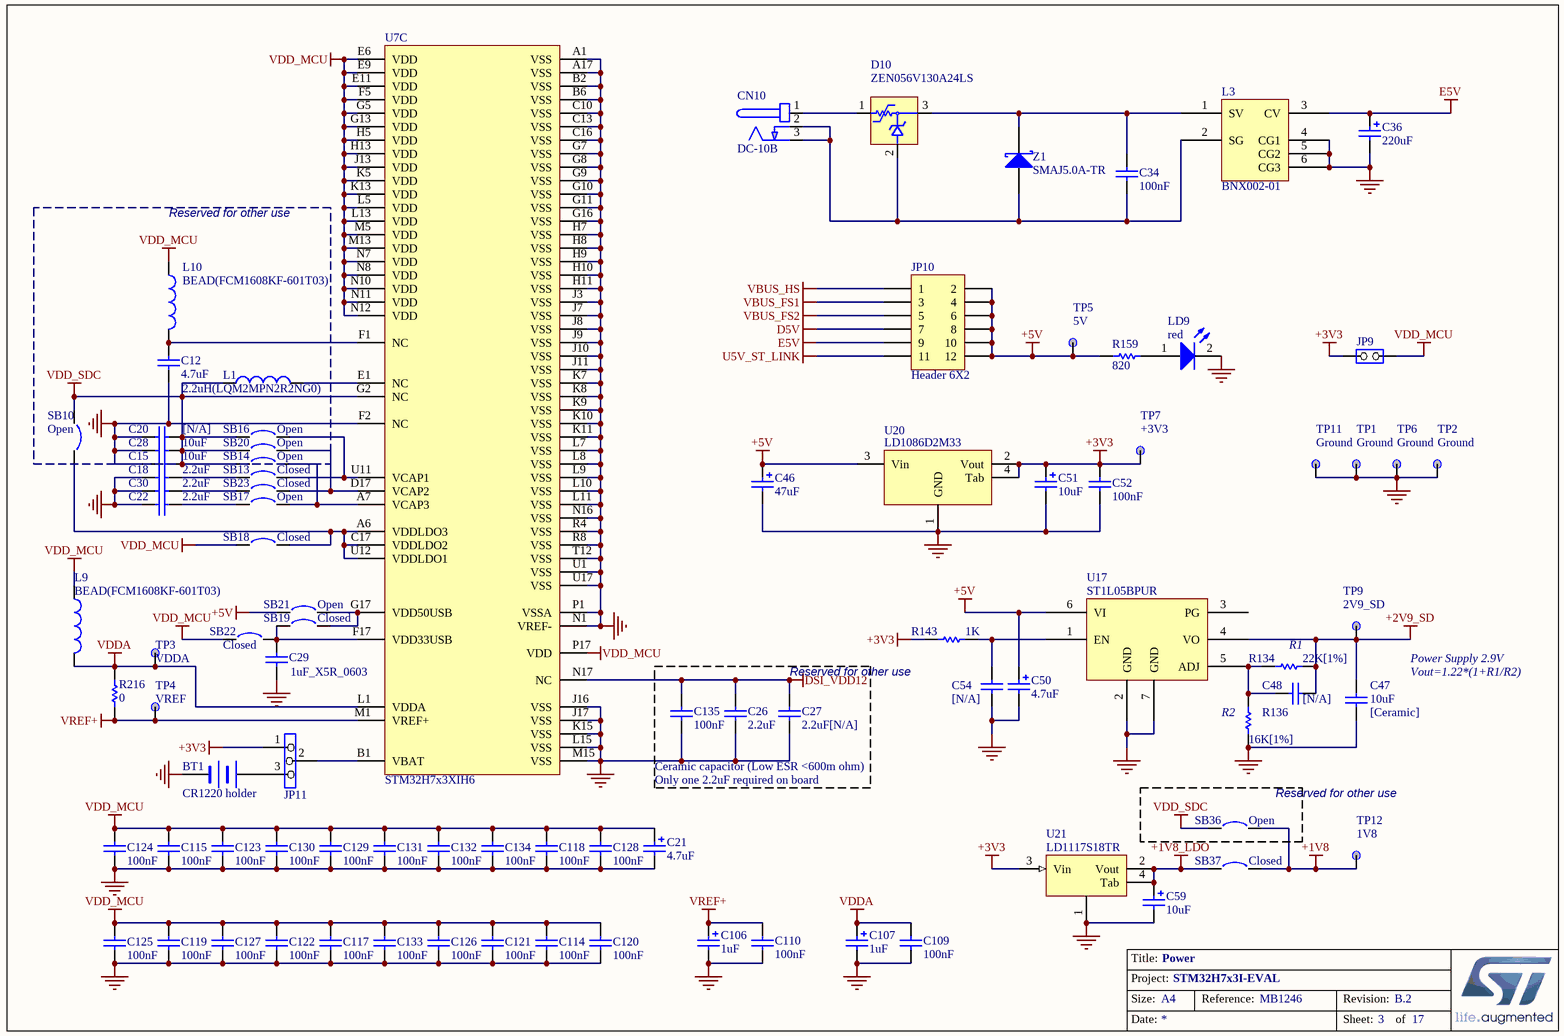
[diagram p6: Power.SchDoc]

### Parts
BT1  CR1220 holder  [BAT_2SM_CR1220]
C12  4.7uF  [0603C]
C15  10uF  [0603C]
C18  2.2uF  [0603C]
C20  [N/A]  [0603C]
C21  4.7uF  [TAN-A]
C22  2.2uF  [0603C]
C26  2.2uF  [0402C]
C27  2.2uF[N/A]  [1206C]
C28  10uF  [0603C]
C29  1uF_X5R_0603  [0603C]
C30  2.2uF  [0603C]
C34  100nF  [0603C]
C36  220uF  [c310m-6]
C46  47uF  [CAE_5R3X5R3_H5R4]
C47  10uF  [0603C]
C48  [N/A]  [0603C]
C50  4.7uF  [TAN-A]
C51  10uF  [TAN-A]
C52  100nF  [0603C]
C54  [N/A]  [0603C]
C59  10uF  [TAN-A]
C106  1uF  [TAN-A]
C107  1uF  [TAN-A]
C109  100nF  [0402C]
C110  100nF  [0402C]
C114  100nF  [0402C]
C115  100nF  [0402C]
C117  100nF  [0402C]
C118  100nF  [0402C]
C119  100nF  [0402C]
C120  100nF  [0402C]
C121  100nF  [0402C]
C122  100nF  [0402C]
C123  100nF  [0402C]
C124  100nF  [0402C]
C125  100nF  [0402C]
C126  100nF  [0402C]
C127  100nF  [0402C]
C128  100nF  [0402C]
C129  100nF  [0402C]
C130  100nF  [0402C]
C131  100nF  [0402C]
C132  100nF  [0402C]
C133  100nF  [0402C]
C134  100nF  [0402C]
C135  100nF  [0402C]
CN10  DC-10B  [PWR_JACK_DC10]
D10  ZEN056V130A24LS  [TYCO_ZEN056V130A24LS]
JP9  (no value)  [SIP2]
JP10  Header 6X2  [HDR_2X6_2R54]
JP11  (no value)  [SIP3]
L1  2.2uH(LQM2MPN2R2NG0)  [LSM2_VLS2016E_S]
L3  BNX002-01  [BNX001]
L9  BEAD(FCM1608KF-601T03)  [0603L]
L10  BEAD(FCM1608KF-601T03)  [0603L]
LD9  red  [0603D]
R134  22K[1%]  [0603R]
R136  16K[1%]  [0603R]
R143  1K  [0603R]
R159  820  [0603R]
R216  0  [0603R]
SB10  Open  [SB_0603]
SB13  Closed  [SB_0603]
SB14  Open  [SB_0603]
SB16  Open  [SB_0603]
SB17  Open  [SB_0603]
SB18  Closed  [SB_0603]
SB19  Closed  [SB_0603]
SB20  Open  [SB_0603]
SB21  Open  [SB_0603]
SB22  Closed  [SB_0603]
SB23  Closed  [SB_0603]
SB36  Open  [SB_0603]
SB37  Closed  [SB_0603]
TP1  Ground  [TP]
TP2  Ground  [TP]
TP3  VDDA  [TP]
TP4  VREF  [TP]
TP5  5V  [TP]
TP6  Ground  [TP]
TP7  +3V3  [TP]
TP9  2V9_SD  [TP]
TP11  Ground  [TP]
TP12  1V8  [TP]
U7  STM32H7x3XIH6  [BGA265_0R8_14X14_SKT]  (part C of 3)
U17  ST1L05BPUR  [DFN6_0R95_3X3]
U20  LD1086D2M33  [TO263-3]
U21  LD1117S18TR  [SOT-223]
Z1  SMAJ5.0A-TR  [sma]

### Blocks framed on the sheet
Reserved for other use: C12 C15 C20 C28 L1 L10 SB10 SB14 SB16 SB20
Reserved for other use: SB36

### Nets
+1V8: SB36.2 SB37.2 TP12.1
+1V8_LDO: C59.1 SB37.1 U21.2(Vout) U21.4(Tab)
+2V9_SD: C47.1 C48.2 R134.1 TP9.1 U17.4(VO)
+3V3: C51.1 C52.1 JP9.1(COMMON) JP11.1 R143.2 TP7.1 U20.2(Vout) U20.4(Tab) U21.3(Vin)
+5V: C46.1 C50.1 JP10.2 JP10.4 JP10.6 JP10.8 JP10.10 JP10.12 R159.2 SB21.1 TP5.1 U17.6(VI) U20.3(Vin)
D5V: JP10.7
DSI_VDD12: C26.1 C27.1 C135.1 U7.N17(NC)
E5V: C36.1 JP10.9 L3.3(CV)
GND: BT1.2(-) C12.1 C15.1 C18.1 C20.1 C21.2 C22.1 C26.2 C27.2 C28.1 C29.1 C30.1 C36.2 C46.2 C47.2 C50.2 C51.2 C52.2 C54.2 C59.2 C106.2 C107.2 C109.1 C110.1 C114.2 C115.2 C117.2 C118.2 C119.2 C120.2 C121.2 C122.2 C123.2 C124.2 C125.2 C126.2 C127.2 C128.2 C129.2 C130.2 C131.2 C132.2 C133.2 C134.2 C135.2 L3.4(CG1) L3.5(CG2) L3.6(CG3) LD9.2(K) R136.2 TP1.1 TP2.1 TP6.1 TP11.1 U7.A1(VSS) U7.A17(VSS) U7.B2(VSS) U7.B6(VSS) U7.C10(VSS) U7.C13(VSS) U7.C16(VSS) U7.F2(NC) U7.G7(VSS) U7.G8(VSS) U7.G9(VSS) U7.G10(VSS) U7.G11(VSS) U7.G16(VSS) U7.H7(VSS) U7.H8(VSS) U7.H9(VSS) U7.H10(VSS) U7.H11(VSS) U7.J3(VSS) U7.J7(VSS) U7.J8(VSS) U7.J9(VSS) U7.J10(VSS) U7.J11(VSS) U7.J16(VSS) U7.J17(VSS) U7.K7(VSS) U7.K8(VSS) U7.K9(VSS) U7.K10(VSS) U7.K11(VSS) U7.K15(VSS) U7.L7(VSS) U7.L8(VSS) U7.L9(VSS) U7.L10(VSS) U7.L11(VSS) U7.L15(VSS) U7.M15(VSS) U7.N1(VREF-) U7.N16(VSS) U7.P1(VSSA) U7.R4(VSS) U7.R8(VSS) U7.T12(VSS) U7.U1(VSS) U7.U17(VSS) U17.2(GND) U17.7(GND) U20.1(GND) U21.1
U5V_ST_LINK: JP10.11
VBUS_FS1: JP10.3
VBUS_FS2: JP10.5
VBUS_HS: JP10.1
VDD_MCU: C21.1 C114.1 C115.1 C117.1 C118.1 C119.1 C120.1 C121.1 C122.1 C123.1 C124.1 C125.1 C126.1 C127.1 C128.1 C129.1 C130.1 C131.1 C132.1 C133.1 C134.1 JP9.2(NO) L9.1 L10.1 SB18.2 SB22.1 U7.E6(VDD) U7.E9(VDD) U7.E11(VDD) U7.F5(VDD) U7.G5(VDD) U7.G13(VDD) U7.H5(VDD) U7.H13(VDD) U7.J13(VDD) U7.K5(VDD) U7.K13(VDD) U7.L5(VDD) U7.L13(VDD) U7.M5(VDD) U7.M13(VDD) U7.N7(VDD) U7.N8(VDD) U7.N10(VDD) U7.N11(VDD) U7.N12(VDD) U7.P17(VDD)
VDD_SDC: C15.2 C20.2 C28.2 L1.1 SB10.1 SB14.1 SB16.1 SB20.1 SB36.1 U7.G2(NC)
VDDA: C107.1 C109.2 L9.2 R216.1 TP3.1 U7.L1(VDDA)
VREF+: C106.1 C110.2 R216.2 TP4.1 U7.M1(VREF+)
NetBT1_1: BT1.1(+) JP11.3
NetC12_2: C12.2 L10.2 U7.F1(NC)
NetC18_2: C18.2 SB13.2
NetC22_2: C22.2 SB17.1
NetC29_2: C29.2 SB19.1 SB22.2 U7.F17(VDD33USB)
NetC30_2: C30.2 SB23.2
NetC34_1: C34.1 D10.3 L3.1(SV) Z1.2(K)
NetC34_2: C34.2 CN10.2(GND) CN10.3(GND) D10.2 L3.2(SG) Z1.1(A)
NetC48_1: C48.1 R134.2 R136.1 U17.5(ADJ)
NetC54_1: C54.1 R143.1 U17.1(EN)
NetCN10_1: CN10.1(+) D10.1
NetJP11_2: JP11.2 U7.B1(VBAT)
NetL1_2: L1.2 U7.E1(NC)
NetLD9_1: LD9.1(A) R159.1
NetSB10_2: SB10.2 SB18.1 U7.A6(VDDLDO3) U7.C17(VDDLDO2) U7.U12(VDDLDO1)
NetSB13_1: SB13.1 SB16.2 U7.U11(VCAP1)
NetSB14_2: SB14.2 SB17.2 U7.A7(VCAP3)
NetSB19_2: SB19.2 SB21.2 U7.G17(VDD50USB)
NetSB20_2: SB20.2 SB23.1 U7.D17(VCAP2)

Not connected (* = marked no-connect by the designer): U17 3(PG)

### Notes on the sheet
- (near R134) R1
- Reserved for other use
- (near R136) R2
- (near C47) [Ceramic]
- Power Supply 2.9V
- Vout=1.22*(1+R1/R2)
- Ceramic capacitor (Low ESR <600m ohm)
- Only one 2.2uF required on board

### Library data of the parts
BT1 = BATTERY
C12 C15 C18 C20 C22 C27 C28 C30 C47 C48 C52 C54 C109 C110 = Cap: Capacitor; Value: 10nF
C21 C36 = Cap Pol1: Polarized Capacitor (Radial); Value: 47uF
C26 = CAP: Capacitor; Value: 100nF
C29 = CAP SMD 0603  X5R 1µF 25V 10%: 0603  X5R 1µF; Rated voltage: 25V; Tolerance: 10%
C34 = CAP: Capacitor; Value: 100pF
C46 C106 C107 = Cap Pol1: Polarized Capacitor (Radial); Value: 10uF
C50 = Cap Pol1: Polarized Capacitor (Radial); Value: 100pF
C51 C59 = Cap Pol1: Polarized Capacitor (Radial)
C114 C115 C117-C135 = CAP: Capacitor
CN10 = PJ202A
JP9 = JP2
JP10 = Header 6X2: Header, 6-Pin, Dual row
JP11 = Jumper3
L1 L9 L10 = Inductor: Value: 100uH
L3 = BNX002
LD9 = LED2: Typical RED, GREEN, YELLOW, AMBER GaAs LED
R134 R136 R216 = Res1: Resistor; Value: 1K
R143 = res1: Resistor
R159 = res1: Resistor; Value: 1K
SB10 SB14 SB16 SB17 SB20 SB21 SB36 = Circuit Breaker
SB13 SB18 SB19 SB22 SB23 SB37 = Circuit Breaker_close: Circuit Breaker
TP1-TP7 TP9 TP11 TP12 = TP
U7 = STM32H7x3XIH6_TFBGA265
U17 = ST1L05
U20 = VOLTREG1
U21 = LD1117
Z1 = D Schottky: Schottky Diode; Code - JEDEC: DO-214-AA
